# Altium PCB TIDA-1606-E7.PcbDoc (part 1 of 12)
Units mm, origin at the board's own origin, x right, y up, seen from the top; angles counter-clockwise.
Board outline 270 x 345 mm, 4 copper layers (Top Layer, Signal Layer 1, Signal Layer 2, Bottom Layer), stack 2.326 mm thick; 1282 components, 576 nets, 3628 pads, 4132 vias.
Unrouted connection lines stored in the file: 1719.
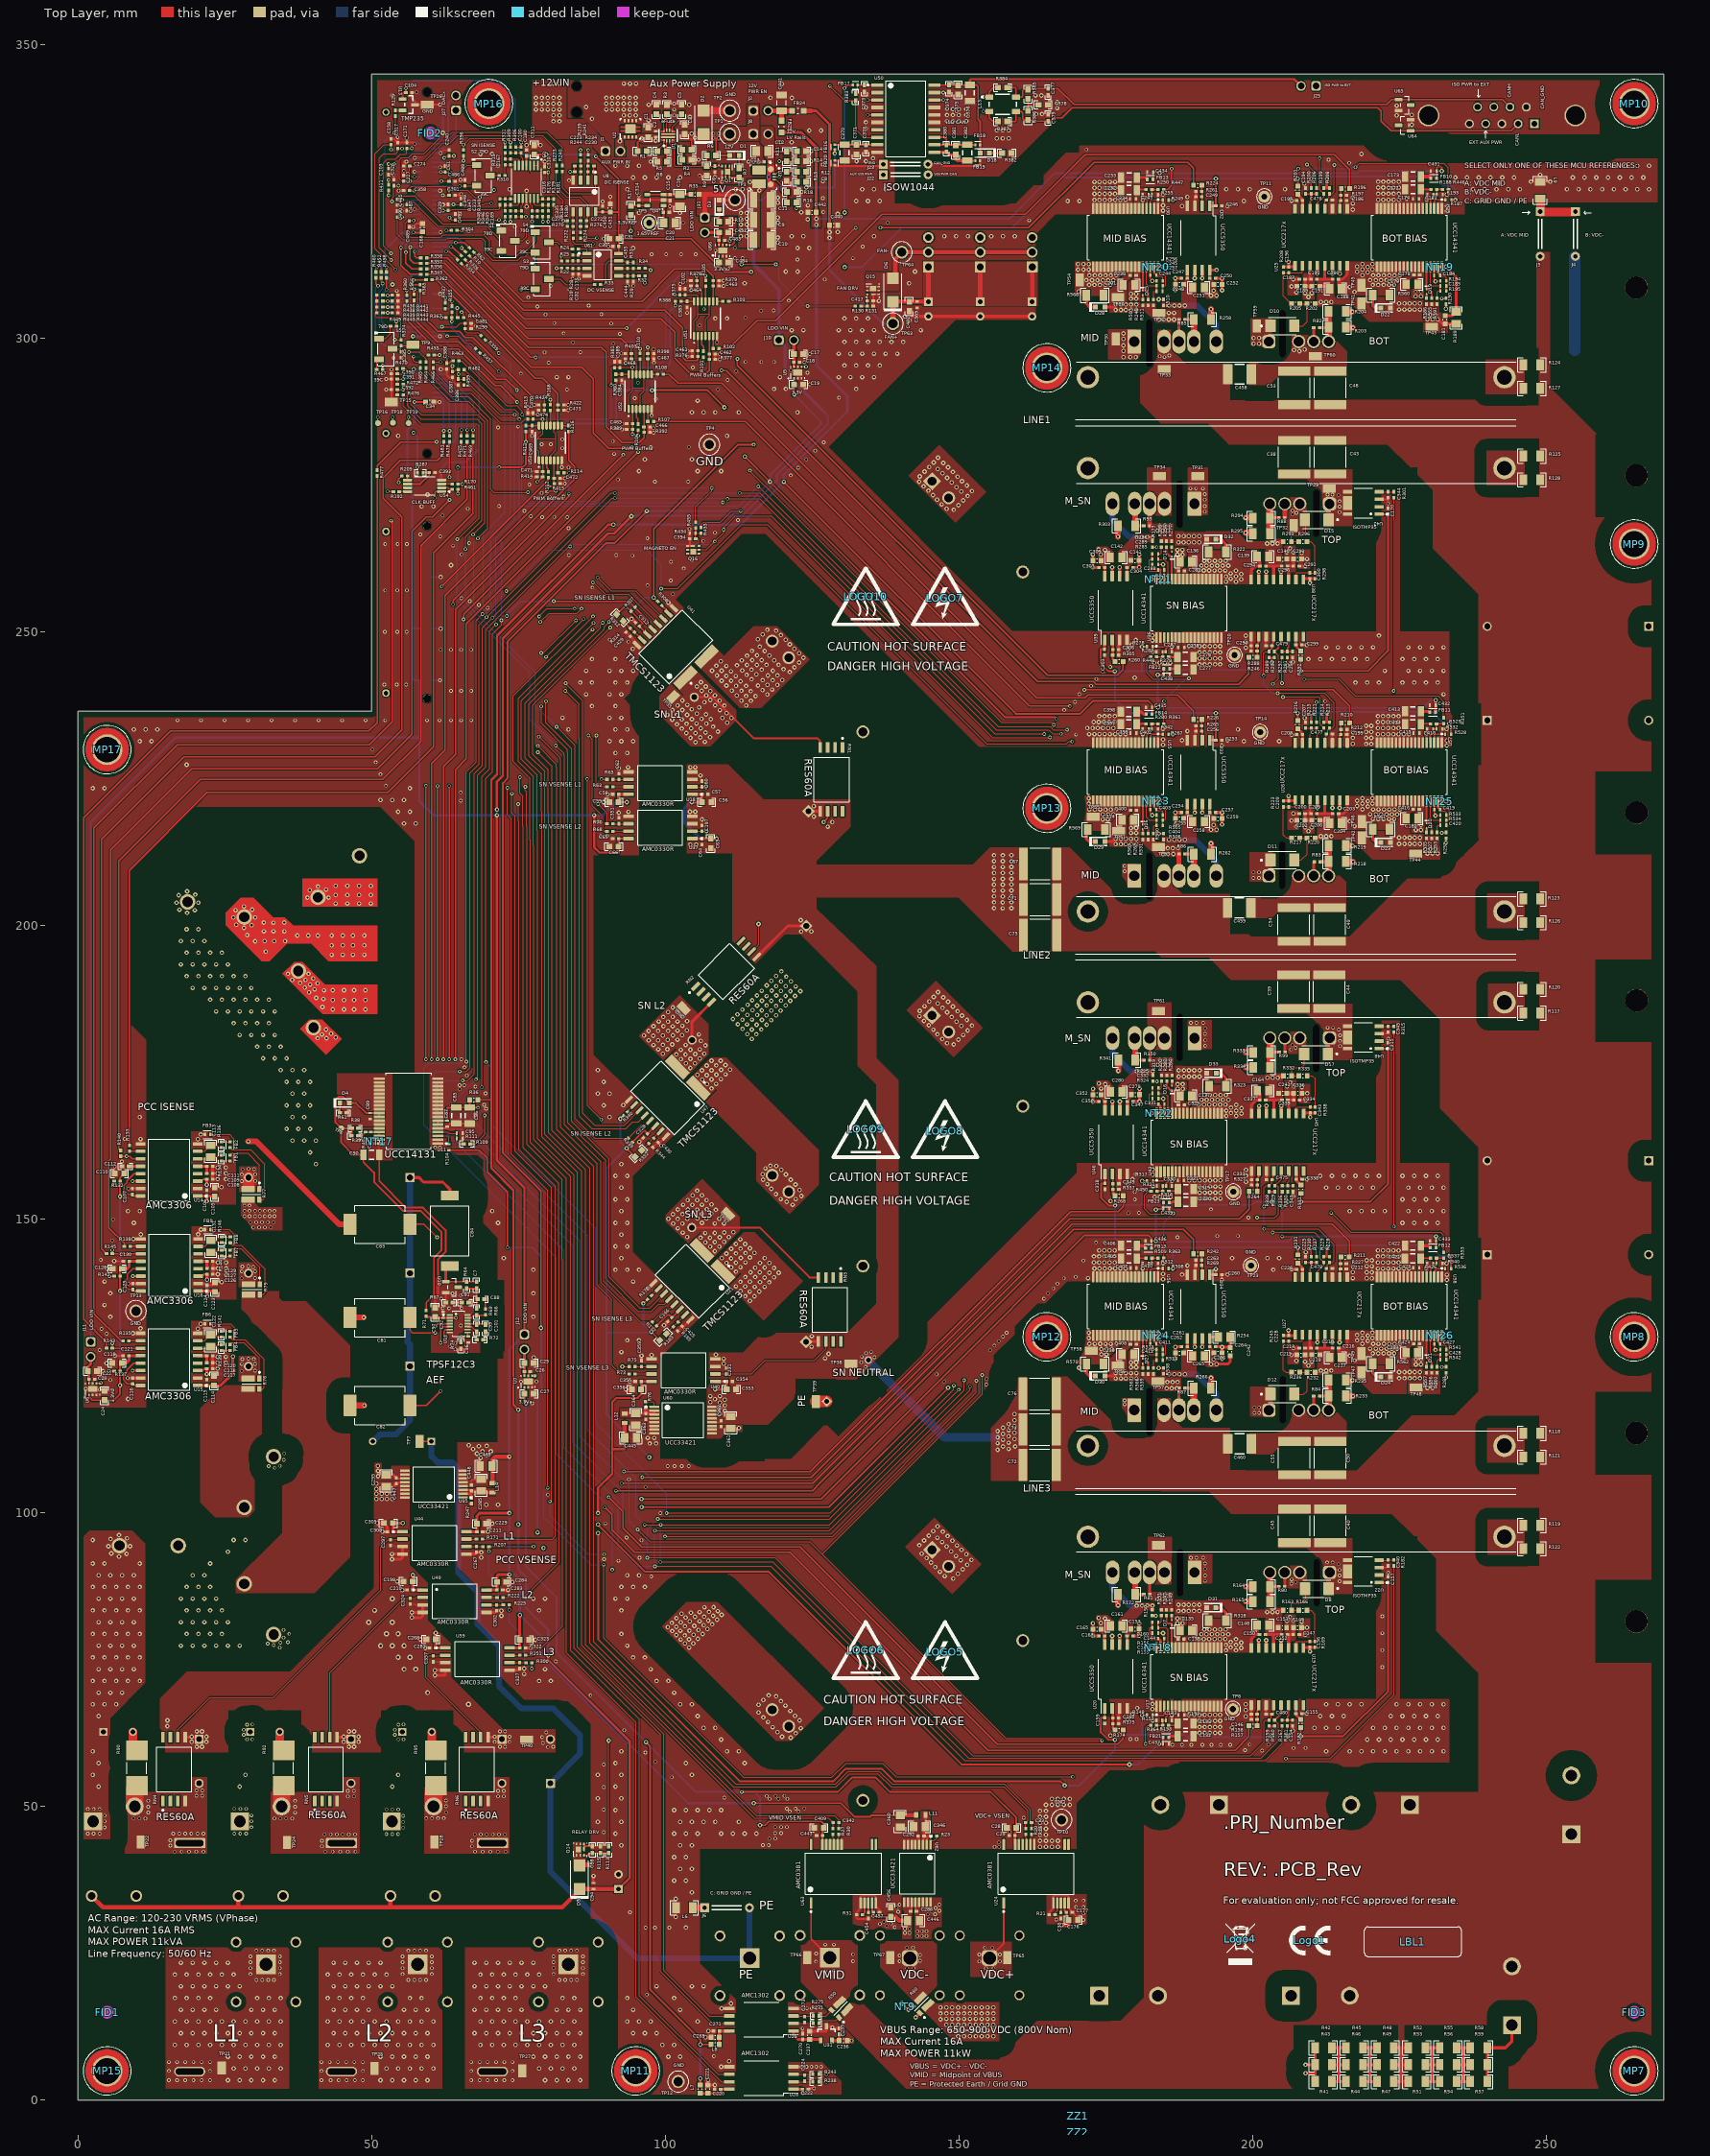
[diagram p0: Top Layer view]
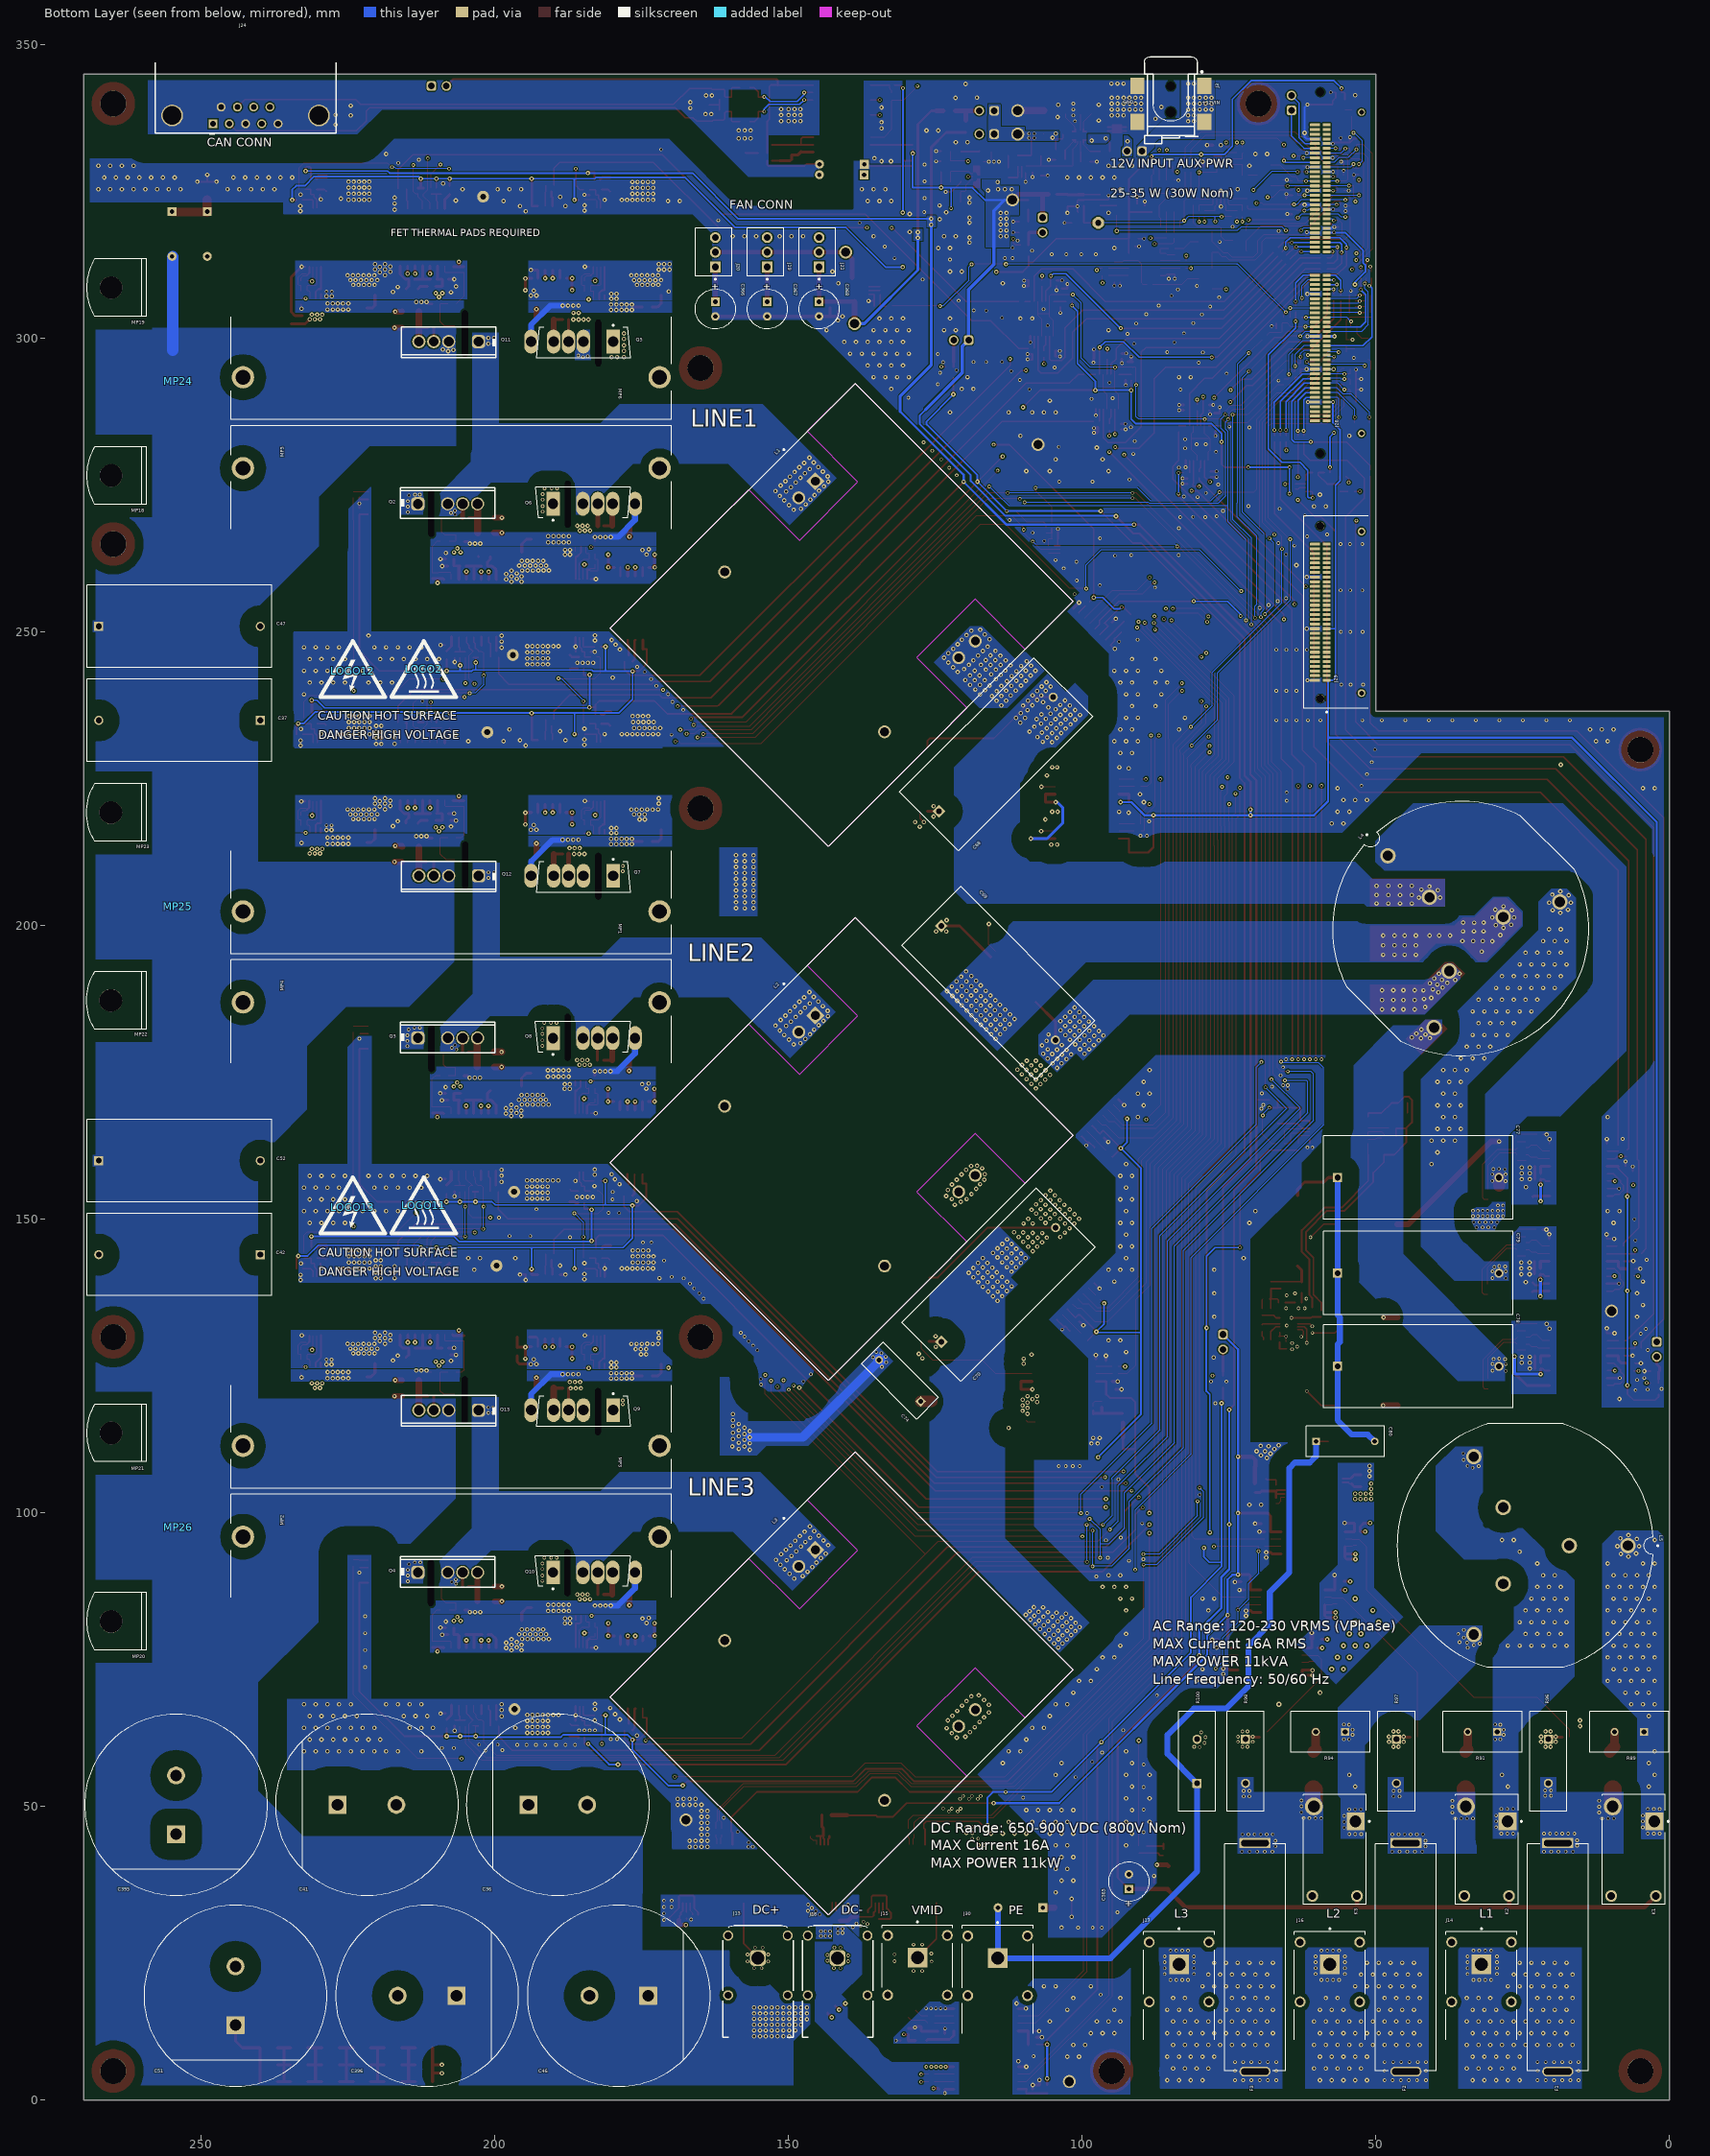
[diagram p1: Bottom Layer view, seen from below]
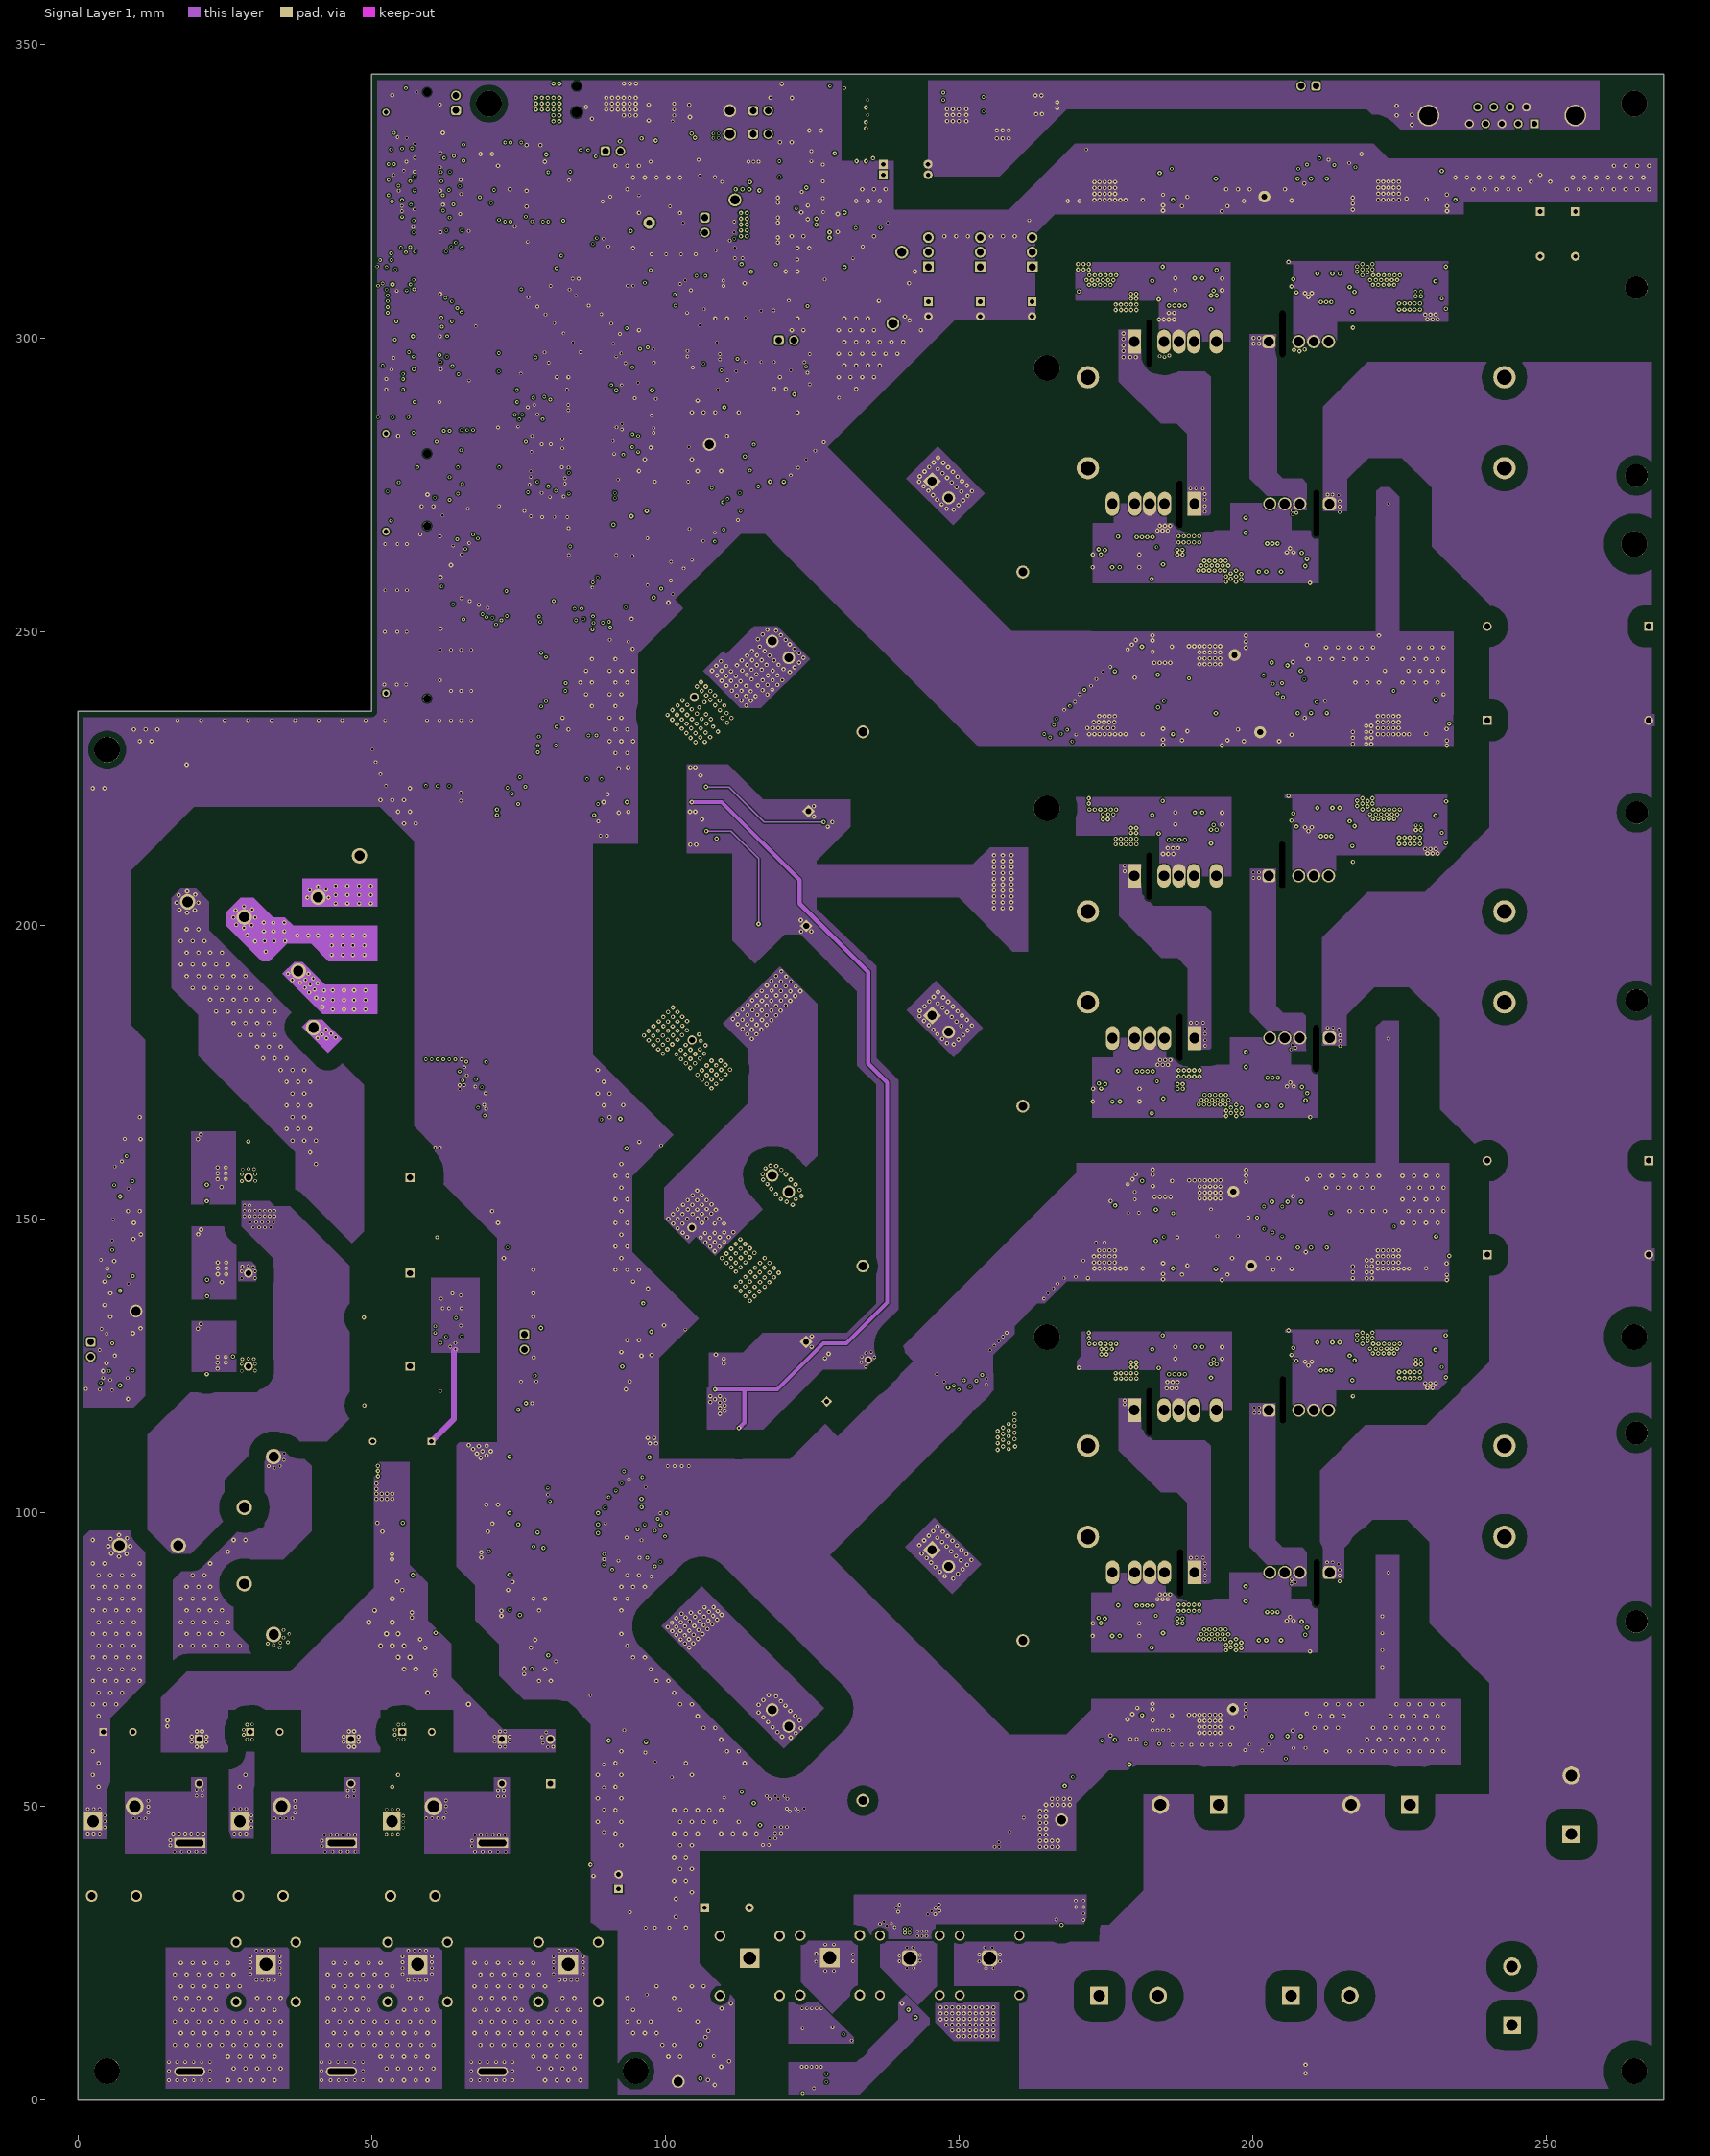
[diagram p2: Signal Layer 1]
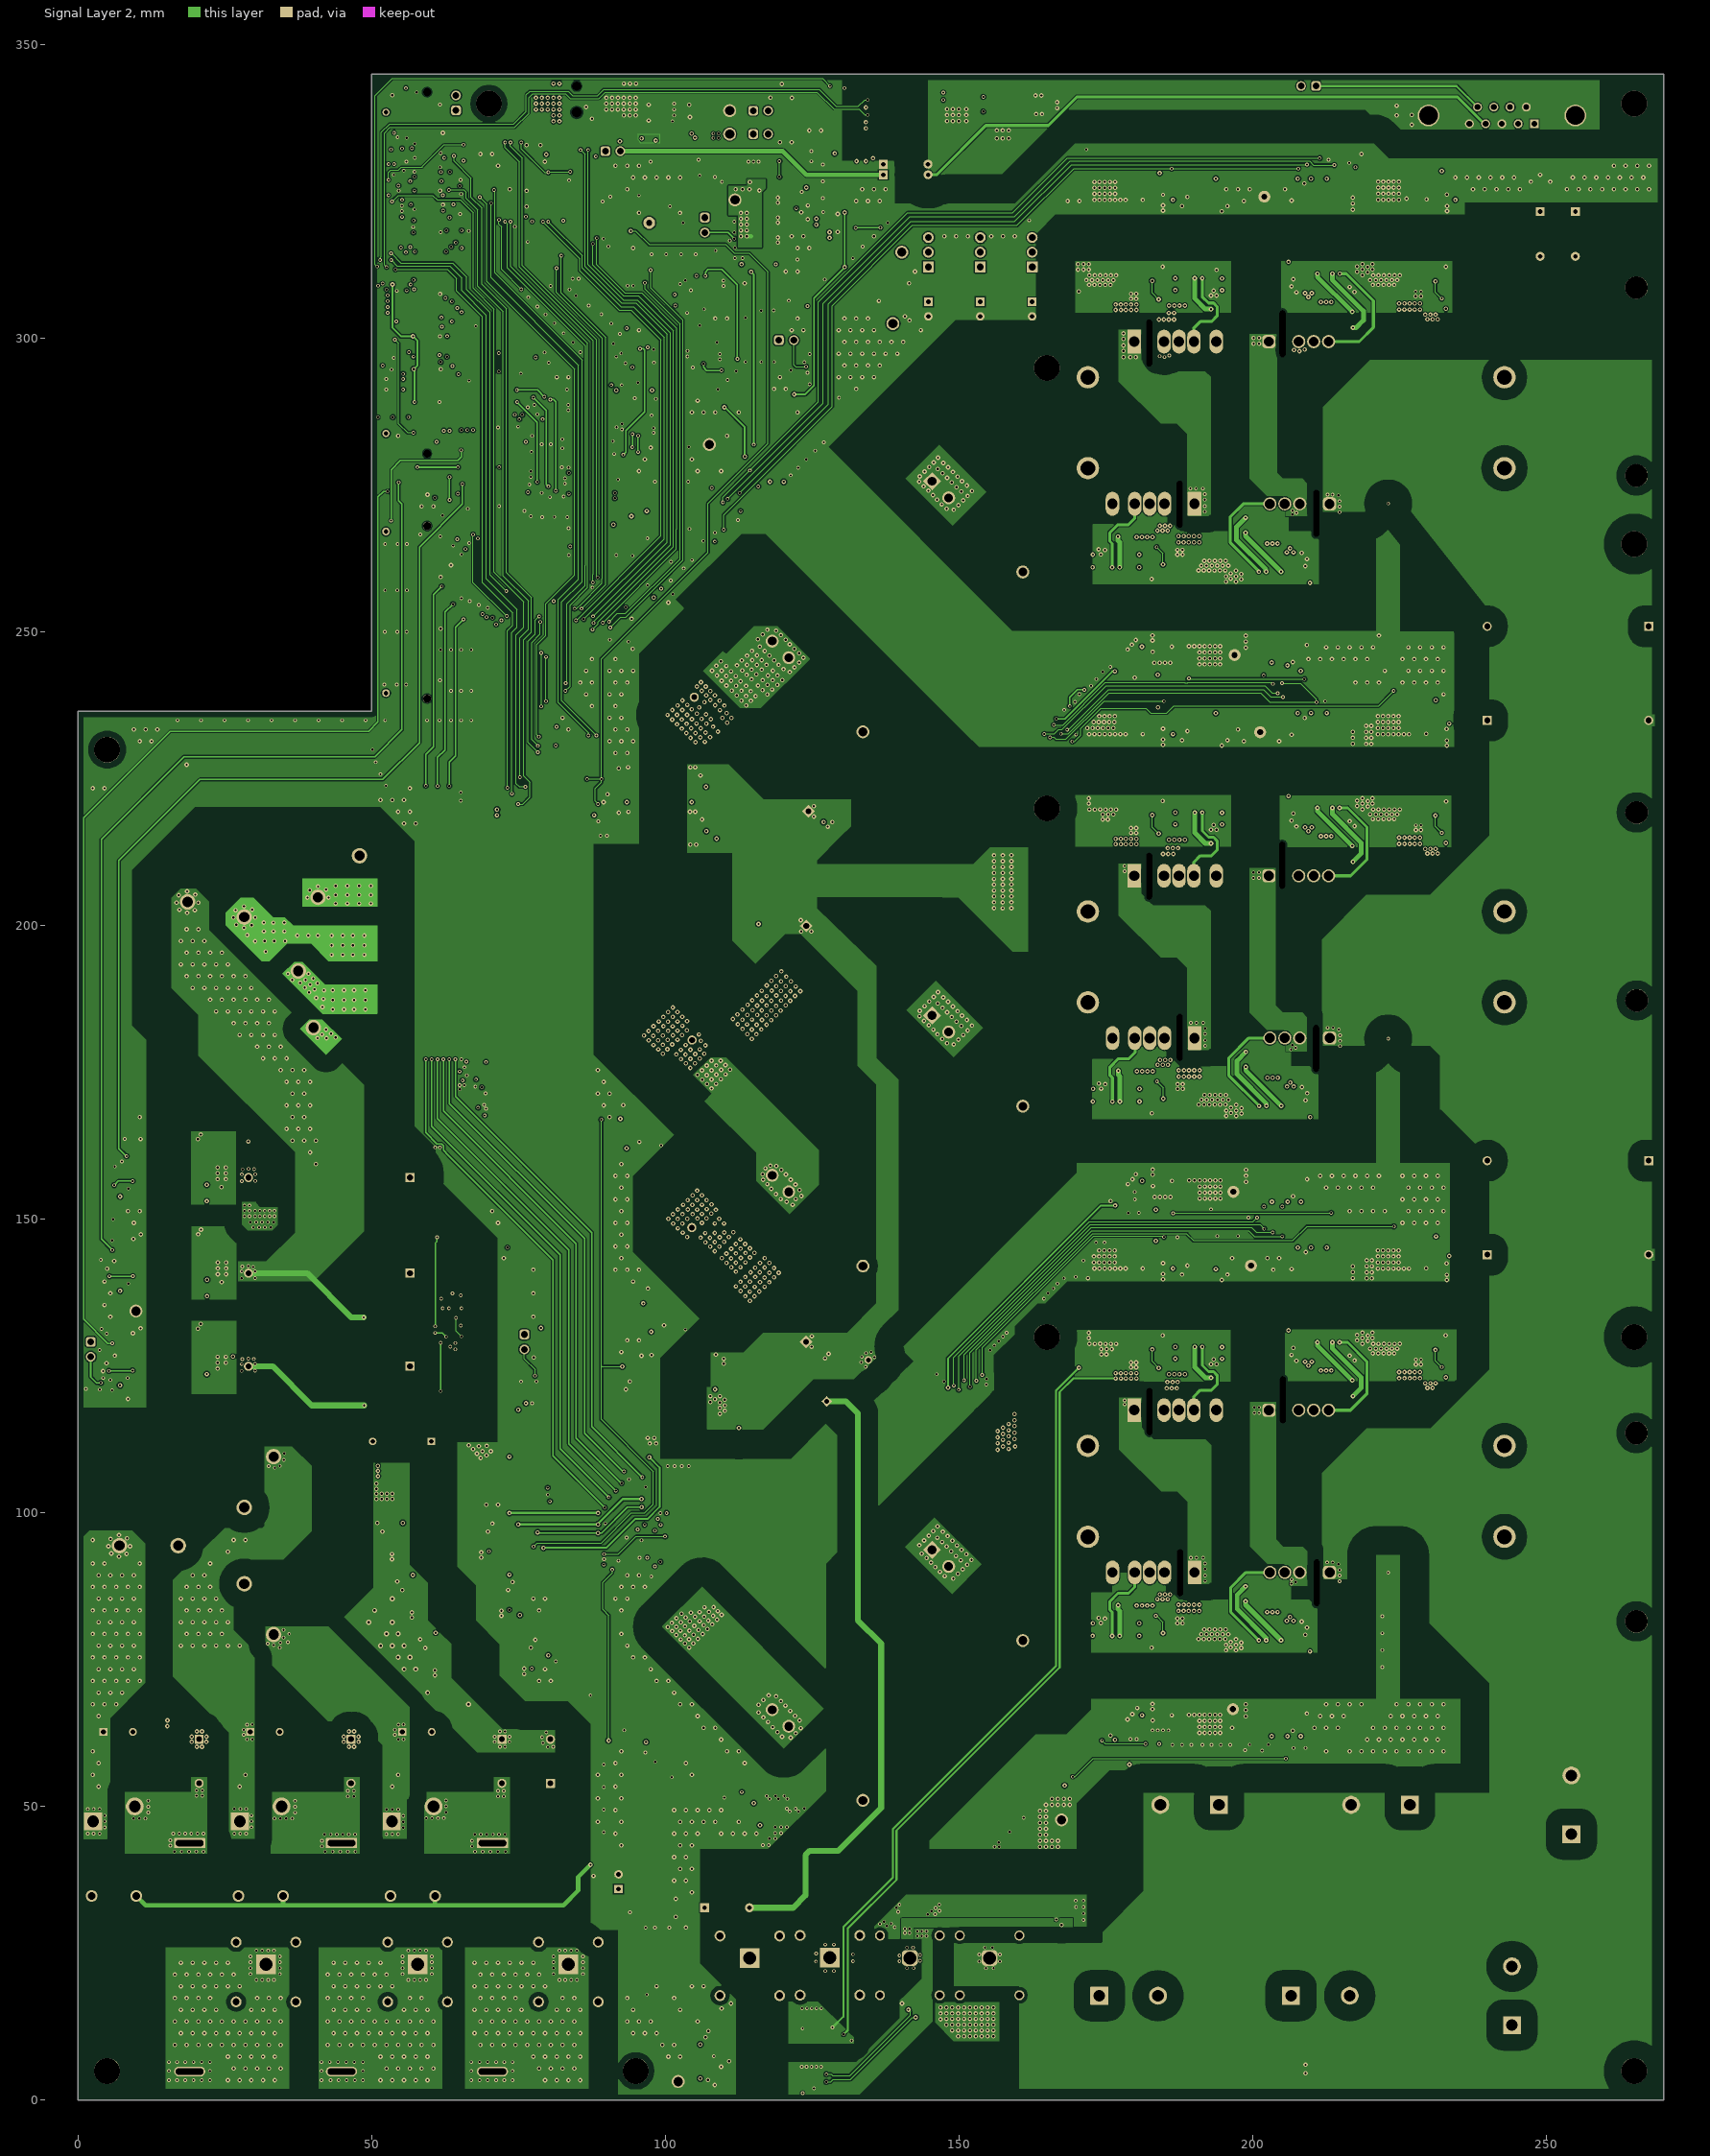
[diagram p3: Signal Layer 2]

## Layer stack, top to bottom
Top Solder: solder mask 0.01, Solder Resist, Dk 3.5
Top Layer: signal copper 0.06
Dielectric 1: prepreg 0.36, FR-4, Dk 4.2
Signal Layer 1: signal copper 0.07
Dielectric 2: core 1.3462, FR-4, Dk 4.2
Signal Layer 2: signal copper 0.07
Dielectric 3: prepreg 0.36, FR-4, Dk 4.2
Bottom Layer: signal copper 0.06
Bottom Solder: solder mask 0.01, Solder Resist, Dk 3.5

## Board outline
0,0 270.002,0 270,0 270,345 50,345 50,236.5 0,236.5

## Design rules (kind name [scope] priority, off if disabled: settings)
AcuteAngle AcuteAngle_room [InNet('+5V') and WithinRoom('Room_DCDC')] p1: minimum=1.00000000000000E+0001 checktracksonly=FALSE
AcuteAngle [All] p2: minimum=4.50000000000000E+0001 checktracksonly=TRUE
AssemblyTestPointUsage [All] p1: valid=2
BoardOutlineClearance BoardOutlineClearance_Poly [OnCopper and IsPoly] p1: gap=1 ignorepadtopadclearanceinfootprint=FALSE
BoardOutlineClearance [OnCopper and Not InComponentClass('Logo') and not InComponentClass('FiducialMark') and not InRegion(1000,500,4000,800) and not InPoly and not (StringText = '.Layer_Name')] p2: gap=0.5 ignorepadtopadclearanceinfootprint=FALSE
Clearance "NT room" [WithinRoom('NT_Room')] p1: gap=0.203 ignorepadtopadclearanceinfootprint=TRUE except(0.003: Arc-Arc Arc-Track Track-Track)
Clearance HV_I_V_SENSE_LOW [InNetClass('HV_VDC_LOW') vs InNetClass('HV_VDC_LOW')] p2: gap=0.203 ignorepadtopadclearanceinfootprint=TRUE
Clearance HV_I_SENSE_MID [InNetClass('HV_VDC_MID') vs InNetClass('HV_VDC_MID')] p3: gap=0.203 ignorepadtopadclearanceinfootprint=TRUE
Clearance HV_ISENSE_SN_PCC_1 [InNetClass('HV_L1') vs InNetClass('HV_L1')] p4: gap=0.203 ignorepadtopadclearanceinfootprint=TRUE
Clearance HV_ISENSE_SN_PCC_2 [InNetClass('HV_L2') vs InNetClass('HV_L2')] p5: gap=0.203 ignorepadtopadclearanceinfootprint=TRUE
Clearance HV_ISENSE_SN_PCC_3 [InNetClass('HV_L3') vs InNetClass('HV_L3')] p6: gap=0.203 ignorepadtopadclearanceinfootprint=TRUE
Clearance HV_VSENSE_SN [InNetClass('HV_VSEN_SN') vs InNetClass('HV_VSEN_SN')] p7: gap=0.203 ignorepadtopadclearanceinfootprint=TRUE
Clearance HV_VSENSE_PCC [InNetClass('HV_VSEN_PCC') vs InNetClass('HV_VSEN_PCC')] p8: gap=0.203 ignorepadtopadclearanceinfootprint=TRUE
Clearance HV_CAN [InNetClass('HV_CAN') vs InNetClass('HV_CAN')] p9: gap=0.203 ignorepadtopadclearanceinfootprint=TRUE
Clearance HV_AEF [InNetClass('AEF_GRID_GND') vs InNetClass('AEF_GRID_GND')] p10: gap=0.203 ignorepadtopadclearanceinfootprint=TRUE
Clearance HV_HV_1206_BleedR [InNetClass('HV_Nets') vs WithinRoom('Bleed_Room')] p11: gap=1.8 ignorepadtopadclearanceinfootprint=TRUE except(3: Arc-Fill Arc-Poly Arc-Region Track-Fill Track-Poly Track-Region SMDPad-Fill SMDPad-Poly SMDPad-Region THPad-Fill THPad-Poly THPad-Region Via-Fill Via-Poly Via-Region Fill-Fill Fill-Poly Fill-Region Poly-Poly Poly-Region Region-Region)
Clearance HV_Slot [InNetClass('HV_Nets') vs (ObjectKind = 'Pad') And (Net = 'No Net') And (Component = 'Free')] p12: gap=0.381 ignorepadtopadclearanceinfootprint=TRUE
Clearance HV_HV_Diode [HasFootprint('FP-US1Q-TP_SMA-MFG') vs InNetClass('HV_Nets') and ispad] p13: gap=2.8 ignorepadtopadclearanceinfootprint=TRUE except(2.4: SMDPad-SMDPad SMDPad-THPad)
Clearance HV_HV [InNetClass('HV_Nets') vs InNetClass('HV_Nets')] p14: gap=2.8 ignorepadtopadclearanceinfootprint=TRUE
Clearance HV_AC1 [InNetClass('HV_AC1') vs InNetClass('HV_AC1')] p15: gap=3 ignorepadtopadclearanceinfootprint=TRUE
Clearance GRID_GND_LV [InNet('GRID_GND') vs InNetClass('LV Nets')or InNetClass('LV_DIGITAL')] p16: gap=3 ignorepadtopadclearanceinfootprint=TRUE
Clearance GRID_AEF_LV [InNetClass('AEF_GRID_GND') vs InNetClass('LV Nets')or InNetClass('LV_DIGITAL')] p17: gap=3 ignorepadtopadclearanceinfootprint=TRUE
Clearance HV_LV_ISOTMP [InNetClass('HV_Nets') vs WithinRoom('RoomDefinition_ISOTMP_3')or WithinRoom('RoomDefinition_ISOTMP_2')or WithinRoom('RoomDefinition_ISOTMP_1')] p18: gap=3.8 ignorepadtopadclearanceinfootprint=TRUE
Clearance HV_LV [InNetClass('LV Nets') vs InNetClass('HV_Nets') or InNetClass('HV_AC1')] p19: gap=5 ignorepadtopadclearanceinfootprint=TRUE
Clearance HVAC_LV_Digital [InNetClass('LV_DIGITAL') vs InNetClass('HV_AC1')or InNetClass('HV_Nets')] p20: gap=5 ignorepadtopadclearanceinfootprint=TRUE
Clearance HV_Heatsink [InNetClass('HV_Nets') vs InNetClass('HV_Heatsink')] p21: gap=2 ignorepadtopadclearanceinfootprint=TRUE
Clearance HV_HW_Footprints_CLR [InNetClass('HV_Nets') vs HasFootprint('fp-613_MNT_BRACKET-MFG') or HasFootprint('FP-C247-075-3AE_PTH_HTSNK_75MM0_18MM0-MFG') or HasFootprint('FP-B181108 D6665 V2_PTH_IND_52MM5_59MM0-MFG')] p22: gap=1.5 ignorepadtopadclearanceinfootprint=TRUE
Clearance HV_HW_Footprints_CLR_1 [InNetClass('LV Nets') vs HasFootprint('fp-613_MNT_BRACKET-MFG') or HasFootprint('FP-C247-075-3AE_PTH_HTSNK_75MM0_18MM0-MFG') or HasFootprint('FP-B181108 D6665 V2_PTH_IND_52MM5_59MM0-MFG')] p23: gap=1.5 ignorepadtopadclearanceinfootprint=TRUE
Clearance HV_Footprints_CLR_Standoff [InNetClass('HV_Nets') vs HasFootprint('FP-9774040960R_ROUND_SPACER_6MM0-MFG')] p24: gap=3 ignorepadtopadclearanceinfootprint=TRUE
Clearance LV_Footprints_CLR_Standoff [HasFootprint('FP-9774040960R_ROUND_SPACER_6MM0-MFG') vs InNetClass('LV Nets')] p25: gap=1 ignorepadtopadclearanceinfootprint=TRUE
Clearance HV_Footprints_CONN_1 [InNetClass('All Nets') vs HasFootprint('Cliff_FCR7350R')or HasFootprint('Cliff_FCR7350B')] p26: gap=0.6 ignorepadtopadclearanceinfootprint=TRUE
Clearance HV_Footprints_CONN [InNetClass('All Nets') vs HasFootprint('FP-FCR7350Y_CONN_BANANA_JACK-MFG') or HasFootprint('FP-FCR7350N_CONN_BANANA_JACK-MFG') or HasFootprint('FP-FCR7350G_CONN_BANANA_JACK-MFG')] p27: gap=0.75 ignorepadtopadclearanceinfootprint=TRUE
Clearance LV_HF [InNetClass('LV_HF') vs InNetClass('All Nets')] p28: gap=0.4 ignorepadtopadclearanceinfootprint=TRUE
Clearance LV_LV [InNetClass('LV_DIGITAL') vs InNetClass('LV Nets')or InNetClass('LV_DIGITAL')] p29: gap=0.203 ignorepadtopadclearanceinfootprint=TRUE
Clearance Room_CLR_efuse [WithinRoom('Room_eFuse')] p30: gap=0.203 ignorepadtopadclearanceinfootprint=TRUE except(0.152: Arc-Via Arc-Text Track-Via Track-Text SMDPad-Via SMDPad-Text THPad-Via THPad-Text Via-Via Via-Text Fill-Text Poly-Text Region-Text Text-Text; 0.196: SMDPad-Fill SMDPad-Poly SMDPad-Region THPad-Fill THPad-Poly THPad-Region Via-Fill Via-Poly Via-Region)
Clearance Room_CLR_LDO [WithinRoom('LDORoom_1') or WithinRoom('LDORoom_2') or WithinRoom('LDORoom_3') or WithinRoom('LDORoom_4')] p31 off: gap=0.114 ignorepadtopadclearanceinfootprint=TRUE
Clearance Room_CLR_DCDC [WithinRoom('Room_DCDC')] p32: gap=0.178 ignorepadtopadclearanceinfootprint=TRUE except(0.089: Fill-Region; 0.102: SMDPad-Region; 0.254: Arc-Poly Track-Poly SMDPad-Poly THPad-Poly Via-Poly Fill-Poly Poly-Poly)
Clearance Clearance_Poly_Efuse [InPolygon vs InNet('+12V_OUT')or InNet('VIN_PWR')] p33: gap=0.152 ignorepadtopadclearanceinfootprint=TRUE
Clearance Clearance_FiducialMark [IsKeepOut and InComponentClass('FiducialMark') vs InComponentClass('FiducialMark') and ispad] p34: gap=0 ignorepadtopadclearanceinfootprint=FALSE
Clearance Clearance_Keepouts [((IsTrack Or IsArc) And Not InPoly) And IsFree and IsKeepOut vs ((IsTrack Or IsArc) And Not InPoly) And IsFree and IsKeepOut] p35: gap=0 ignorepadtopadclearanceinfootprint=FALSE
Clearance Clearance_Keepouts_1 [(ObjectKind = 'Pad') And (Net = 'No Net') vs IsKeepOut] p36: gap=0 ignorepadtopadclearanceinfootprint=FALSE
Clearance Clearance_Keepouts_2 [All vs IsKeepOut] p37: gap=0.5 ignorepadtopadclearanceinfootprint=FALSE
Clearance [All] p38: gap=0.203 ignorepadtopadclearanceinfootprint=TRUE
ComponentClearance ComponentClearance_3DBody [(ObjectKind = '3D Body') And (Identifier = 'TMDSCNCD280039C_PCB')] p1: gap=-0.025 collisioncheckmode=3 verticalgap=0.254 showdistances=FALSE
ComponentClearance ComponentClearance_HeatSink_FET_1 [HasFootprint('FP-C247-075-3AE_PTH_HTSNK_75MM0_18MM0-MFG')] p2: gap=-0.254 collisioncheckmode=3 verticalgap=-0.254 showdistances=TRUE
ComponentClearance ComponentClearance_THtoTH [IsThruComponent vs IsThruComponent] p3: gap=0.508 collisioncheckmode=3 verticalgap=0.762 showdistances=FALSE
ComponentClearance ComponentClearance_Net-tie [(ComponentType = 'Net Tie')] p4: gap=-0.025 collisioncheckmode=3 verticalgap=0.254 showdistances=FALSE
DiffPairsRouting [All] p1: maxlimit=2.54 minlimit=0.254 mostfreqgap=0.254 toplayer_minwidth=0.381 toplayer_maxwidth=0.381 toplayer_prefwidth=0.381 midlayer1_minwidth=0.381 midlayer1_maxwidth=0.381 midlayer1_prefwidth=0.381 midlayer2_minwidth=0.381 midlayer2_maxwidth=0.381 midlayer2_prefwidth=0.381 bottomlayer_minwidth=0.381 bottomlayer_maxwidth=0.381 bottomlayer_prefwidth=0.381 maxuncoupledlength=25.4
FabricationTestPointUsage TestPointUsage [All] p1: valid=2 allowmultiple=FALSE
FabricationTestpoint Testpoint [All] p1: side=3 testpointundercomponent=TRUE minsize=1.016 maxsize=2.54 preferedsize=1.524 minholesize=0 maxholesize=1.016 preferedholesize=0.813 testpointgrid=0.025 allowsidetop=TRUE allowsidebottom=TRUE usegrid=TRUE gridtolerance=0
FanoutControl Fanout_LCC [IsLCC] p1: bgadir=Out bgaviamode=Centered fanoutstyle=Auto fanoutdirection=Alternating viagrid=0.025 // Fanout_LCC (Default Rule)
FanoutControl Fanout_BGA [IsBGA] p2: bgadir=Out bgaviamode=Centered fanoutstyle=Auto fanoutdirection=Alternating viagrid=0.025 // Fanout_BGA (Default Rule)
FanoutControl Fanout_Default [All] p4: bgadir=Out bgaviamode=Centered fanoutstyle=Auto fanoutdirection=Alternating viagrid=0.025 // Fanout_Default (Default Rule)
FanoutControl Fanout_Small [(CompPinCount < 5)] p5: bgadir=Out bgaviamode=Centered fanoutstyle=Auto fanoutdirection=OutThenIn viagrid=0.025 // Fanout_Small (Default Rule)
HoleSize [All] p1: absolutevalues=TRUE maxlimit=8.2 minlimit=0.152 maxpercent=80.000 minpercent=20.000
MinimumAnnularRing MinimumAnnularRing_Room [WithinRoom('Romm_TVS')or WithinRoom('Room_eFuse')] p1: minimumring=0.076
MinimumAnnularRing [All] p2: minimumring=0.127
MinimumAnnularRing MinimumAnnularRing_ThermalPadVias [IsVia and InAnyComponent] p3: minimumring=0.15
MinimumSolderMaskSliver MinimumSolderMaskSliver_Logo [InComponentClass('Logo') vs InComponentClass('Logo')] p1: minsoldermaskwidth=0.018
MinimumSolderMaskSliver [All] p2: minsoldermaskwidth=0.064
PlaneConnect [All] p1: planeconnectstyle=Relief reliefexpansion=0.254 reliefentries=4 reliefconductorwidth=0.254 reliefairgap=0.254
PolygonConnect [All] p1: connectstyle=Direct reliefconductorwidth=0.254 reliefentries=4 polygonreliefangle="90 Angle" airgapwidth=0.254
RoomDefinition NT_Room [False] p1: confinementstyle=ConfineIn formatcopy=TRUE lockcomponents=FALSE outline 139.852,16.764 141.961,16.764 141.961,14.935 139.852,14.935
RoomDefinition Bleed_Room [False] p2: confinementstyle=ConfineIn formatcopy=TRUE lockcomponents=FALSE outline 203.251,13.716 243.815,13.716 243.815,0.965 203.251,0.965
RoomDefinition Romm_TVS [False] p3: confinementstyle=ConfineIn formatcopy=TRUE lockcomponents=FALSE outline 92.12,337.5 96.25,337.5 96.25,333.825 92.12,333.825
RoomDefinition Room_DCDC [False] p4: confinementstyle=ConfineIn formatcopy=TRUE lockcomponents=FALSE outline 114.619,329.603 119,329.603 119,325.453 114.619,325.453
RoomDefinition RoomDefinition_ISOTMP_2 [False] p5: confinementstyle=ConfineIn formatcopy=TRUE lockcomponents=FALSE outline 215.329,183.361 225.995,183.361 225.995,176.861 215.329,176.861
RoomDefinition RoomDefinition_ISOTMP_1 [False] p6: confinementstyle=ConfineIn formatcopy=TRUE lockcomponents=FALSE outline 215.253,274.376 225.918,274.376 225.918,267.876 215.253,267.876
RoomDefinition RoomDefinition_ISOTMP_3 [False] p7: confinementstyle=ConfineIn formatcopy=TRUE lockcomponents=FALSE outline 215.129,92.9 225.795,92.9 225.795,86.4 215.129,86.4
RoomDefinition Room_eFuse [InComponentClass('U_TIDA-1606-E6_Hardware')] p8: confinementstyle=ConfineIn formatcopy=TRUE lockcomponents=FALSE outline 99.067,335.951 102.046,335.951 102.046,333.175 99.067,333.175
RoutingVias Room_RoutingVias [WithinRoom('Romm_TVS')or WithinRoom('Room_eFuse')] p1: holewidth=0.305 width=0.61 viastyle="Through Hole" minholewidth=0.152 minwidth=0.254 maxholewidth=1.016 maxwidth=1.651
RoutingVias ThermalPadVias [IsVia and InAnyComponent] p2: holewidth=0.305 width=0.508 viastyle="Through Hole" minholewidth=0.198 minwidth=0.381 maxholewidth=1.016 maxwidth=0.61
RoutingVias [All] p3: holewidth=0.305 width=0.61 viastyle="Through Hole" minholewidth=0.254 minwidth=0.508 maxholewidth=1.016 maxwidth=1.651
SilkToBoardRegionClearance [Not ((IsComment or IsDesignator) And (Hide <> 'False')) and not InRegion(1000,500,4000,800)] p1:
SilkToSilkClearance SilkToSilkClearance_Pb-FreeLogo [(HasFootprint('Pb-Free_Overlay_Medium') OR HasFootprint('Pb-Free_Overlay_Small')) vs (HasFootprint('Pb-Free_Overlay_Medium') OR HasFootprint('Pb-Free_Overlay_Small'))] p1: silktosilkclearance=0
SilkToSilkClearance [All] p2: silktosilkclearance=0.076
SilkToSolderMaskClearance SilkToSolderMasPad_CLR_Exception [IsPad vs InComponent('J1')] p1 off: minsilkscreentomaskgap=0 clearancetoexposedcopper=TRUE
SilkToSolderMaskClearance SilkToComponentPadClearance [(ObjectKind = 'Pad') And (Component = 'Free')] p2: minsilkscreentomaskgap=0 clearancetoexposedcopper=TRUE
SilkToSolderMaskClearance SilkToComponentPadClearance_1 [IsPad and not (Component = 'Free') vs not IsArc] p3: minsilkscreentomaskgap=0.006 clearancetoexposedcopper=TRUE
SilkToSolderMaskClearance "Silk to Solder Mask Opening" [IsPad vs not IsArc] p4: minsilkscreentomaskgap=0.025 clearancetoexposedcopper=FALSE
SolderMaskExpansion [All] p1: expansion=0.05
UnRoutedNet [All] p1: checkbadconnections=TRUE
Width [InNetClass('All Nets')] p1: maxlimit=7 minlimit=0.127 preferedwidth=0.152
14 further rules are at their usual default settings.

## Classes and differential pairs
net class AEF_GRID_GND: +12V_AEF_ISO AEF_INJ AEF_INJ_CM AEF_SENS1 AEF_SENS2 AEF_SENS3 AEF_TVS_PT AEF_VDD FB_AEF GRID_GND NetC88_1 NetC91_1 NetC99_1 NetC99_2 NetC101_1 NetD4_1 NetR38_1 NetU10_3 NetU12_1 NetU12_3 NetU12_12 VEEA_UCC_AEF
net class HV_CAN: CAN_GND2 CANH CANHI CANL CANLO GND_ISO_CAN NetC378_2 NetD18_1 NetJ24_1 NetJ24_8 NetU50_14 NetU64_3 NetU65_3 VIN_PWR_CAN VISOOUT VP_CAN VP_CAN_SUBD
net class HV_VDC_MID: 3.3V_ISO_MID3 +15V_MID1 +15V_MID2 +15V_MID3 -4V_MID1 -4V_MID2 -4V_MID3 FBVDD_MID1 FBVDD_MID2 FBVDD_MID3 FBVEE_MID1 FBVEE_MID2 FBVEE_MID3 GATE_MID_L1 GATE_MID_L2 GATE_MID_L3 I_MID+ I_MID- NetD25_2 NetD26_2 NetD27_2 NetD28_1 NetD29_1 NetD30_1 OUTH_MID_L1 OUTH_MID_L2 OUTH_MID_L3 REF_MID1 REF_MID2 REF_MID3 RLIM_MID1 RLIM_MID2 RLIM_MID3 VDC_MID VDC_MID_IN VEEA_MID1 VEEA_MID2 VEEA_MID3 VINN_VMD VINP_VMD
net class HV_VDC_LOW: +5VISO_DC- +15V_VDC-1 +15V_VDC-2 +15V_VDC-3 -4V_VDC-1 -4V_VDC-2 -4V_VDC-3 FBVDD_VDC-1 FBVDD_VDC-2 FBVDD_VDC-3 FBVEE_VDC-1 FBVEE_VDC-2 FBVEE_VDC-3 GATE_BOT_L1 GATE_BOT_L2 GATE_BOT_L3 I_NEG_RAIL+ I_NEG_RAIL- NetC35_2 NetC196_1 NetC209_1 NetC228_1 NetC454_2 NetD10_2 NetD11_2 NetD12_2 NetD19_2 NetD20_2 NetD21_2 NetD22_1 NetD23_1 NetD24_1 NetR21_1 NetR31_1 OH_BOT_L1 OH_BOT_L2 OH_BOT_L3 OL_BOT_L1 OL_BOT_L2 OL_BOT_L3 REF_VDC-1 REF_VDC-2 REF_VDC-3 RLIM_VDC-1 RLIM_VDC-2 RLIM_VDC-3 VDC- VDC-_REF VDC_NEG_IN VEEA_VDC-1 VEEA_VDC-2 VEEA_VDC-3 VINN_DC- VINP_DC-
net class HV_VSEN_PCC: +5VISO_PCC V_PCC_IN1 V_PCC_IN2 V_PCC_IN3 V_PCC_N
net class HV_VSEN_SN: +5VISO_SN NetRN3_7 NetRN3_8 V_SN_IN1 V_SN_IN2 V_SN_IN3 V_SN_N
net class LV_HF: GATE_MID_L1 GATE_MID_L2 GATE_MID_L3 GATE_MID_SN_L1 GATE_TOP_L1 OUTH_MID_L1 OUTH_MID_L2 OUTH_MID_L3 OUTH_MID_SN_L1 OUTH_TOP_L1 OUTL_TOP_L1
net class LV_DIGITAL: \EN_DCDC_GATES BUFF_EN CAN_EN CAN_RX CAN_TX CANEN_IO CANRX_IO CANTX_IO EN_DC_IO EN_DCDC_GATES_BUF EN_RY_IO FAN_CTRL FAN_CTRL_BU FLT_BU G_FLT1_IO G_FLT2_IO G_FLT3_IO G_RDY_IO G_RST_IO GATES_FLT_L1 GATES_FLT_L2 GATES_FLT_L3 GATES_RDY GATES_RST ID_A ID_B ID_C ID_D NetJ26_45 NetJ26_46 NetJ26_50 NetJ26_58 NetJ26_60 NetJ26_64 NetR437_1 OC1_IO OC2_IO OC3_IO OC_L1 OC_L2 OC_L3 PIN76 PIN96 PWM1_BUF_L1 PWM1_BUF_L2 PWM1_BUF_L3 PWM1_L1 PWM1_L2 PWM1_L3 PWM1L1 PWM1L2 PWM1L3 PWM2_BUF_L1 PWM2_BUF_L2 PWM2_BUF_L3 PWM2_L1 PWM2_L2 PWM2_L3 PWM2L1 PWM2L2 PWM2L3 PWM3_BUF_L1 PWM3_BUF_L2 PWM3_BUF_L3 PWM3_L1 PWM3_L2 PWM3_L3 PWM3L1 PWM3L2 PWM3L3 PWM4_BUF_L1 PWM4_BUF_L2 PWM4_BUF_L3 PWM4_L1 PWM4_L2 PWM4_L3 PWM4L1 PWM4L2 PWM4L3 RY_N SD_CLKI SD_CLKI_IN_L1 SD_CLKI_IN_L2 SD_CLKI_IN_L3 SD_CLKI_OUT_L1 SD_CLKI_OUT_L2 SD_CLKI_OUT_L3 SD_Data_I_PCC_L1 SD_Data_I_PCC_L2 SD_Data_I_PCC_L3
net class "LV Nets": 1.65V 3.3VREF +3V3 +3V3_Ua +3V3_Ua2 +3V3_Ud +5V +12V +12V_FAN ALERT_L1 ALERT_L2 ALERT_L3 AMC1302_OUTN_A AMC1302_OUTN_B AMC1302_OUTP_A AMC1302_OUTP_B CAN_EN CAN_GND1 CAN_RX CAN_TX CAN_VDD CAN_VIO DC_RVSEN+ DC_RVSEN- DC_VSEN+ DC_VSEN- DCM_RVSEN+ DCM_RVSEN- DCM_VSEN+ DCM_VSEN- GND I_SENSE_SN_L1 I_SENSE_SN_L2 I_SENSE_SN_L3 I_SENSE_VDC_MID I_SENSE_VDC_NEG NetC100_2 NetC167_2 NetC169_2 NetC313_2 NetC316_2 NetC335_2 NetJ26_89 NetR23_2 OC_L1 OC_L2 OC_L3 OP_ISN1 OP_ISN2 OP_ISN3 PIN25_AIN PIN27_AIN PIN34_AIN PIN36_AIN PIN40_AIN SN_Relays TEMP_SENSE_AMB TEMP_SENSE_L1 TEMP_SENSE_L2 TEMP_SENSE_L3 TMCS_VO_L1 TMCS_VO_L2 TMCS_VO_L3 TMCS_VREF1 TMCS_VREF2 TMCS_VREF3 V_SENSE_MID_DC- V_SENSE_MID_DC-_0039C V_SENSE_PCC_L1 V_SENSE_PCC_L2 V_SENSE_PCC_L3 V_SENSE_SN_L1 V_SENSE_SN_L2 V_SENSE_SN_L3 VIN_PWR VINP_DC-_HAVOK
net class HV_Heatsink: MP1 MP2 MP3 MP4 MP5 MP6 NetMP1_2 NetMP2_1 NetMP3_2 NetMP4_1 NetMP5_1 NetMP6_2
net class HV_L3: +15V_SN_L3 -4V_SN_L3 AEF_CHK_3 AMC_DC_OUT3 AMC_HGND_L3 CHK_3 DESAT_BOT_L3 FBVDD_SN_L3 FBVEE_SN_L3 GATE_MID_SN_L3 GATE_TOP_L3 I_PCC_INN_L3 I_PCC_INP_L3 I_PCC_L3+ I_PCC_L3- I_SN_L3+ I_SN_L3- NetC127_1 NetC156_1 NetD7_2 NetD8_2 NetD31_1 NetFB7_2 NetFB8_2 OUTH_MID_SN_L3 OUTH_TOP_L3 OUTL_TOP_L3 REF_SN_L3 RLIM VEEA_SN_L3
net class HV_L2: +15V_SN_L2 -4V_SN_L2 AEF_CHK_2 AMC_DC_OUT2 AMC_HGND_L2 CHK_2 DESAT_BOT_L2 FBVDD_SN_L2 FBVEE_SN_L2 GATE_MID_SN_L2 GATE_TOP_L2 I_PCC_INN_L2 I_PCC_INP_L2 I_PCC_L2+ I_PCC_L2- I_SN_L2+ I_SN_L2- NetC118_1 NetC343_1 NetD16_2 NetD17_2 NetD33_1 NetFB4_2 NetFB5_2 OUTH_MID_SN_L2 OUTH_TOP_L2 OUTL_TOP_L2 REF_SN_L2 RLIM_SN_L2 VEEA_SN_L2
net class HV_L1: +15V_SN_L1 -4V_SN_L1 AEF_CHK_1 AMC_DC_OUT1 AMC_HGND_L1 CHK_1 DESAT_BOT_L1 FBVDD_SN_L1 FBVEE_SN_L1 GATE_MID_SN_L1 GATE_TOP_L1 I_PCC_INN_L1 I_PCC_INP_L1 I_PCC_L1+ I_PCC_L1- I_SN_L1+ I_SN_L1- NetC109_1 NetD14_2 NetD15_2 NetD32_1 NetFB1_2 NetFB2_2 OC_TOP_L1 OUTH_MID_SN_L1 OUTH_TOP_L1 OUTL_TOP_L1 REF_SN_L1 RLIM_SN_L1 VEEA_SN_L1
net class HV_AC1: +5VISO_PCC +5VISO_SN +12V_AEF_ISO AEF_CHK_1 AEF_CHK_2 AEF_CHK_3 AEF_CHK_N AEF_INJ AEF_INJ_CM AEF_SENS1 AEF_SENS2 AEF_SENS3 AEF_TVS_PT AEF_VDD AMC_DC_OUT1 AMC_DC_OUT2 AMC_DC_OUT3 AMC_HGND_L1 AMC_HGND_L2 AMC_HGND_L3 CHK_1 CHK_2 CHK_3 FB_AEF GRID_GND I_PCC_INN_L1 I_PCC_INN_L2 I_PCC_INN_L3 I_PCC_INP_L1 I_PCC_INP_L2 I_PCC_INP_L3 I_PCC_L1+ I_PCC_L1- I_PCC_L2+ I_PCC_L2- I_PCC_L3+ I_PCC_L3- I_SN_L1+ I_SN_L1- I_SN_L2+ I_SN_L2- I_SN_L3+ I_SN_L3- NetC88_1 NetC91_1 NetC99_1 NetC99_2 NetC101_1 NetC109_1 NetC118_1 NetC127_1 NetD4_1 NetFB1_2 NetFB2_2 NetFB4_2 NetFB5_2 NetFB7_2 NetFB8_2 NetR38_1 PCC_L1 PCC_L2 PCC_L3 PTCR_L1 PTCR_L2 PTCR_L3 RLAY_1 RLAY_2 RLAY_3 V_PCC_IN1 V_PCC_IN2 V_PCC_IN3 V_PCC_L1 V_PCC_L2 V_PCC_L3 V_PCC_N V_SN_IN1 V_SN_IN2 V_SN_IN3 V_SN_N VEEA_UCC_AEF
net class STAND_OFFS: NetMP7_1 NetMP8_1 NetMP9_1 NetMP10_1 NetMP11_1 NetMP12_1 NetMP13_1 NetMP14_1 NetMP15_1 NetMP16_1 NetMP17_1
net class HV_Nets: 3.3V_ISO_MID3 +5VISO_DC- +15V_MID1 +15V_MID2 +15V_MID3 +15V_SN_L1 +15V_SN_L2 +15V_SN_L3 +15V_VDC-1 +15V_VDC-2 +15V_VDC-3 -4V_MID1 -4V_MID2 -4V_MID3 -4V_SN_L1 -4V_SN_L2 -4V_SN_L3 -4V_VDC-1 -4V_VDC-2 -4V_VDC-3 AEF_CHK_N CAN_GND2 CANH CANHI CANL CANLO DESAT_BOT_L1 DESAT_BOT_L2 DESAT_BOT_L3 FBVDD_MID1 FBVDD_MID2 FBVDD_MID3 FBVDD_SN_L1 FBVDD_SN_L2 FBVDD_SN_L3 FBVDD_VDC-1 FBVDD_VDC-2 FBVDD_VDC-3 FBVEE_MID1 FBVEE_MID2 FBVEE_MID3 FBVEE_SN_L1 FBVEE_SN_L2 FBVEE_SN_L3 FBVEE_VDC-1 FBVEE_VDC-2 FBVEE_VDC-3 GATE_BOT_L1 GATE_BOT_L2 GATE_BOT_L3 GATE_MID_L1 GATE_MID_L2 GATE_MID_L3 GATE_MID_SN_L1 GATE_MID_SN_L2 GATE_MID_SN_L3 GATE_TOP_L1 GATE_TOP_L2 GATE_TOP_L3 GND_ISO_CAN GRID_GND I_MID+ I_MID- I_NEG_RAIL+ I_NEG_RAIL- L1_MID_DRAIN L2_MID_DRAIN L3_MID_DRAIN NetC35_2 NetC156_1 NetC196_1 NetC209_1 NetC228_1 NetC343_1 NetC378_2 NetC454_2 NetD7_2 NetD8_2 NetD10_2 NetD11_2 NetD12_2 NetD14_2 NetD15_2 NetD16_2 NetD17_2 NetD18_1 NetD19_2 NetD20_2 NetD21_2 NetD22_1 NetD23_1 NetD24_1 NetD25_2 NetD26_2 NetD27_2 NetD28_1 NetD29_1 NetD30_1 NetD31_1 NetD32_1 NetD33_1 NetR21_1 NetR31_1 NetR41_1 NetR44_1 NetR51_1 NetR54_1 OC_TOP_L1 OH_BOT_L1 OH_BOT_L2 OH_BOT_L3 OL_BOT_L1 OL_BOT_L2 OL_BOT_L3 OUTH_MID_L1 OUTH_MID_L2 OUTH_MID_L3 OUTH_MID_SN_L1 OUTH_MID_SN_L2 OUTH_MID_SN_L3 OUTH_TOP_L1 OUTH_TOP_L2 OUTH_TOP_L3 OUTL_TOP_L1 OUTL_TOP_L2 OUTL_TOP_L3 PCC_L1 PCC_L2 PCC_L3 REF_MID1 REF_MID2 REF_MID3 REF_SN_L1 REF_SN_L2 REF_SN_L3 REF_VDC-1 REF_VDC-2 REF_VDC-3 RLIM RLIM_MID1 RLIM_MID2 RLIM_MID3 RLIM_SN_L1 RLIM_SN_L2 RLIM_VDC-1 RLIM_VDC-2 RLIM_VDC-3 V_PCC_L1 V_PCC_L2 V_PCC_L3 V_PCC_N V_SN_N VDC+ VDC- VDC-_REF VDC_MID VDC_MID_IN VDC_NEG_IN VEEA_MID1 VEEA_MID2 VEEA_MID3 VEEA_SN_L1 VEEA_SN_L2 VEEA_SN_L3 VEEA_VDC-1 VEEA_VDC-2 VEEA_VDC-3 VIN_PWR_CAN VINN_DC- VINN_VMD VINP_DC- VINP_VMD VISOOUT VP_CAN VP_CAN_SUBD
component class U_TIDA-1606-SW-Current-Measurements-E7: C100 C166 C167 C169 C180 C310 C311 C312 C313 C316 C328 C329 C335 C425 C429 C430 R176 R177 R178 R179 R180 R181 R183 R184 R185 R306 R307 R308 R309 R310 R311 R312 R313 R314 R339 R340 R344 R345 R346 R347 R348 R349 R352 U9 U21 U41 U47
component class U_TIDA-1606-Switching-Node-L3-E7: C132 C133 C134 C135 C138 C143 C144 C145 C146 C147 C148 C149 C150 C151 C152 C153 C154 C155 C156 C157 C158 C159 C160 C161 C162 C163 C165 C340 C437 C475 D7 D8 D31 FB21 NT18 R80 R81 R147 R148 R149 R150 R151 R152 R153 R155 R156 R157 R158 R159 R160 R161 R162 R163 R164 R165 R166 R167 R169 R172 R174 R175 R182 R318 R364 TP8 U17 U19 U20 U22
component class U_TIDA-1606-Switching-Node-L2-E7: C137 C164 C241 C279 C280 C315 C317 C318 C319 C320 C321 C325 C330 C331 C332 C333 C334 C336 C337 C338 C339 C341 C343 C345 C347 C349 C350 C352 C439 C480 D16 D17 D33 FB23 NT22 R99 R264 R268 R283 R284 R315 R316 R317 R319 R320 R321 R323 R324 R325 R327 R328 R329 R330 R331 R332 R333 R334 R335 R336 R337 R338 R341 R350 R450 TP23 U43 U45 U46 U48
component class U_TIDA-1606-Switching-Node-L1-E7: C136 C139 C140 C141 C142 C170 C171 C276 C277 C278 C282 C287 C288 C289 C290 C291 C293 C294 C296 C298 C299 C300 C303 C304 C306 C307 C309 C344 C438 C479 D14 D15 D32 FB22 NT21 R88 R93 R154 R173 R246 R259 R260 R277 R278 R279 R282 R285 R286 R288 R289 R290 R291 R292 R293 R294 R295 R296 R297 R298 R301 R303 R305 R322 R448 TP20 U36 U38 U39 U42
component class U_TIDA-1606-Middle-Side-E7: C201 C214 C232 C233 C234 C235 C236 C237 C238 C239 C242 C243 C244 C245 C246 C247 C248 C249 C250 C251 C252 C253 C254 C255 C256 C257 C258 C259 C260 C261 C262 C263 C264 C265 C266 C269 C270 C271 C272 C273 C274 C275 C397 C398 C399 C400 C402 C403 C404 C405 C406 C407 C408 C410 C411 C412 C434 C435 C436 D25 D26 D27 D28 D29 D30 FB13 FB14 FB15 L8 NT20 NT23 NT24 R85 R86 R87 R224 R226 R242 R248 R249 R250 R254 R255 R256 R257 R258 R261 R262 R263 R265 R266 R267 R269 R270 R271 R272 R273 R274 R275 R276 R280 R342 R361 R363 R447 R505 R506 R507 R508 R509 R510 R511 R512 R513 R514 R530 R531 R538 R539 R565 R566 R567 R568 R569 R570 TP50 TP51 TP52 TP53 TP54 TP55 TP56 TP57 TP58 U29 U30 U31 U32 U33 U34 U55 U56
component class U_TIDA-1606-Low-Side-E7: C172 C173 C174 C178 C179 C181 C182 C183 C184 C185 C186 C187 C188 C189 C190 C191 C192 C193 C194 C195 C196 C199 C200 C202 C203 C204 C205 C206 C207 C208 C209 C212 C213 C215 C216 C217 C218 C219 C220 C221 C222 C223 C224 C225 C226 C227 C228 C230 C413 C414 C415 C416 C418 C419 C420 C421 C422 C423 C424 C426 C427 C428 C431 C432 C433 C450 C451 C476 C477 C478 D10 D11 D12 D19 D20 D21 D22 D23 D24 FB10 FB11 FB12 L7 NT9 NT19 NT25 NT26 R82 R83 R84 R186 R187 R188 R189 R190 R191 R193 R194 R195 R196 R197 R198 R199 R200 R201 R202 R203 R204 R205 R206 R208 R210 R211 R212 R213 R214 R215 R216 R217 R218 R219 R220 R221 R223 R227 R228 R229 R230 R231 R232 R233 R234 R235 R236 R237 R238 R239 R240 R241 R243 R244 R245 R252 R253 R281 R302 R351 R353 R446 R527 R528 R529 R532 R533 R534 R535 R536 R537 R540 R541 R542 R555 R556 R557 R560 R561 R562 TP11 TP12 TP14 TP17 TP41 TP42 TP43 TP44 TP45 TP46 TP47 TP48 TP49 U8 U23 U25 U26 U27 U28 U57 U58
component class U_TIDA-1606-Hardware-E7: !PCB C103 C104 C366 C367 C368 C369 C401 C417 D6 FID1 FID2 FID3 J19 J20 J21 LBL1 Logo1 LOGO2 Logo3 Logo4 LOGO5 LOGO6 LOGO7 LOGO8 LOGO9 LOGO10 LOGO11 LOGO12 LOGO13 MP1 MP2 MP3 MP4 MP5 MP6 MP7 MP8 MP9 MP10 MP11 MP12 MP13 MP14 MP15 MP16 MP17 MP18 MP19 MP20 MP21 MP22 MP23 MP24 MP25 MP26 Q15 R117 R118 R119 R120 R121 R122 R123 R124 R125 R126 R127 R128 R129 R130 R131 TP63 TP64 U13 ZZ1 ZZ2 ZZ3 ZZ4
component class U_TIDA-1606-SW-Voltage-Measurements-E7: C56 C57 C58 C59 C60 C61 C62 C63 C64 C65 C66 C197 C231 C348 C351 C353 C354 C355 C356 C358 C359 C361 C362 C363 C364 C445 L12 R63 R65 R68 R70 R73 R75 R76 RN1 RN2 RN3 U18 U37 U40 U60
component class U_TIDA-1606-PCC-Voltage-Measurements-E7: C198 C210 C211 C229 C240 C267 C268 C281 C283 C284 C285 C295 C297 C301 C302 C305 C308 C322 C323 C324 C326 C327 C357 C447 C448 C449 L14 R171 R207 R222 R225 R247 R251 R300 RN4 RN5 RN6 U35 U44 U49 U59
component class U_TIDA-1606-DC-Voltage-Measurements-E7: C28 C29 C30 C31 C32 C33 C35 C175 C176 C177 C286 C292 C342 C346 C360 C409 C443 C444 C446 C454 C455 C456 C457 L11 R19 R20 R21 R22 R23 R24 R25 R26 R27 R28 R29 R30 R31 R32 R33 R34 R37 TP10 U24 U61 U62 U63
component class U_TIDA-1606-E7-Aux-Supply: C1 C2 C3 C4 C5 C6 C8 C9 C10 C11 C12 C13 C14 C15 C16 C17 C18 C19 C20 C21 C22 C23 C24 C25 C26 C27 C314 C440 C441 C442 C452 C483 C484 D1 D2 D3 FB24 FB25 J1 J2 J3 J4 J5 J6 J8 J10 J11 J12 J31 L6 L9 Q1 R1 R2 R3 R4 R5 R6 R7 R8 R9 R11 R12 R13 R14 R15 R16 R17 R18 R35 TP1 TP2 TP3 TP4 TP5 U1 U2 U3 U4 U5 U6 U7 U66
component class U_TIDA-1606-Control-Interface-E7: C34 C102 C168 C383 C384 C385 C386 C387 C388 C389 C390 C391 C392 C393 C394 C461 C462 C463 C464 C465 C466 C467 C468 C469 C470 C471 C472 C473 C474 C481 C485 C486 C487 C488 C489 C490 C492 C? J26 J27 J29 Q16 R10 R62 R101 R102 R103 R105 R106 R107 R108 R110 R112 R114 R116 R140 R143 R145 R168 R170 R192 R209 R287 R299 R304 R326 R343 R354 R355 R356 R357 R358 R359 R360 R362 R365 R366 R367 R374 R375 R376 R377 R378 R379 R380 R381 R388 R389 R390 R392 R393 R396 R398 R399 R403 R404 R411 R412 R413 R414 R415 R422 R424 R433 R434 R435 R436 R437 R438 R439 R440 R441 R442 R443 R444 R445 R449 R452 R455 R457 R458 R459 R460 R461 R462 R463 R464 R465 R466 R467 R469 R470 R471 R472 R475 R476 R477 R478 R481 R? S1 S2 S3 S4 S5 S? TP9 TP15 TP16 TP18 TP19 TP26 U51 U52 U53 U54
component class U_TIDA-1606-CAN-Communication-E7: C370 C371 C372 C373 C374 C375 C376 C377 C378 C379 C380 C381 C382 D18 FB16 FB17 FB18 FB19 FB20 J22 J23 J24 J25 L13 R382 R383 R384 R385 R386 R387 U50 U64 U65
component class Label: LBL1
component class Header: J1 J2 J8 J10 J11 J12 J25 J27 J31
component class FiducialMark: FID1 FID2 FID3
component class AssemblyNote: ZZ1 ZZ2 ZZ3 ZZ4
component class U_TIDA-1606-PCC-Current-Measurements-E7: C105 C106 C107 C108 C109 C110 C111 C112 C113 C114 C115 C116 C117 C118 C119 C120 C121 C122 C123 C124 C125 C126 C127 C128 C129 C130 C131 FB1 FB2 FB3 FB4 FB5 FB6 FB7 FB8 FB9 R132 R133 R134 R135 R136 R137 R138 R139 R141 R142 R144 R146 TP13 U14 U15 U16
component class U_TIDA-1606-EMI-Protection-E7: C7 C67 C68 C69 C70 C71 C72 C73 C74 C75 C76 C77 C78 C79 C80 C81 C82 C83 C84 C85 C86 C87 C88 C89 C90 C91 C92 C93 C94 C95 C96 C97 C98 C99 C101 C365 D4 D5 F1 F2 F3 K1 K2 K3 L4 L5 NT17 Q14 R36 R38 R39 R40 R61 R64 R66 R67 R69 R71 R72 R74 R77 R78 R79 R89 R90 R91 R92 R94 R95 R96 R97 R98 R100 R104 R109 R111 R113 R115 TP6 TP7 TP21 TP22 TP24 TP25 TP27 TP28 TP35 TP36 TP37 TP38 TP39 TP40 U10 U11 U12
component class TIDA-1606-Overview-E7: C36 C37 C38 C39 C40 C41 C42 C43 C44 C45 C46 C47 C48 C49 C50 C51 C52 C53 C54 C55 C395 C396 C458 C459 C460 J13 J14 J15 J16 J17 J18 J30 L1 L2 L3 Q2 Q3 Q4 Q5 Q6 Q7 Q8 Q9 Q10 Q11 Q12 Q13 R41 R42 R43 R44 R45 R46 R47 R48 R49 R50 R51 R52 R53 R54 R55 R56 R57 R58 R59 R60 TP29 TP30 TP31 TP32 TP33 TP34 TP59 TP60 TP61 TP62 TP65 TP66 TP67

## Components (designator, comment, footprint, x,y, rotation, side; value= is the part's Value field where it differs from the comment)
C1 "C1608X7R1V105K080AC" 0603 97.13,335.102 r90 top value=1uF
C2 "GCM155R71H104KE02D" 0402S 98.45,334.813 r90 top value=0.1uF
C3 "C1608X7R1V105K080AC" 0603 103.327,335.61 r90 top value=1uF
C4 "GRM188R72A272KA01D" 0603 98.51,339.012 r90 top value=2700pF
C5 "C0603X332K5RACTU" 0603 102.808,339.012 r90 top value=3300pF
C6 "GRM155R71E104KE14D" 0402L 108.479,328.87 r270 top value=0.1uF
C7 "GRM155R71H472KA01D" 0402 67.902,138.801 r270 top value=4700pF
C8 "GRM1885C2A220JA01D" 0603 123.245,326.679 r180 top value=22pF
C9 "GRM32ER71A476KE15L" 1210_270 116.504,320.199 r0 top value=47uF
C10 "GRM32ER71A476KE15L" 1210_270 116.502,316.8 r0 top value=47uF
C11 "GRM32ER71E226KE15L" 1210_270 116.504,323.605 r0 top value=22uF
C12 "EMK212BB7106KG-T" 0805_HV 116.52,331.894 r180 top value=10uF
C13 "GCM155R71H104KE02D" 0402L 117.344,330.1 r0 top value=0.1uF
C14 "C0603C103K4RACTU" 0603 123.245,331.894 r0 top value=0.01uF
C15 "GRM155R71E104KE14D" 0402L 100.845,324 r270 top value=0.1uF
C16 "EMK212BB7106KG-T" 0805_HV 102.54,323.542 r270 top value=10uF
C17 "EMK107BB7225KA-T" 0603 122.72,297.377 r0 top value=2.2uF
C18 "GRM155R71E104KE14D" 0402L 122.42,295.977 r0 top value=0.1uF
C19 "EMK107BB7225KA-T" 0603 122.738,292.171 r0 top value=2.2uF
C20 "GRM155R71E104KE14D" 0402L 100.221,321.5 r0 top value=0.1uF
C21 "EMK212BB7106KG-T" 0805_HV 100.737,319.7 r180 top value=10uF
C22 "EMK107BB7225KA-T" 0603 2.5,124.161 r0 top value=2.2uF
C23 "GRM155R71E104KE14D" 0402L 2.4,122.8 r0 top value=0.1uF
C24 "EMK107BB7225KA-T" 0603 4.588,120.017 r90 top value=2.2uF
C25 "EMK107BB7225KA-T" 0603 76.84,125.532 r0 top value=2.2uF
C26 "GRM155R71E104KE14D" 0402L 76.54,124.108 r0 top value=0.1uF
C27 "EMK107BB7225KA-T" 0603 76.84,120.318 r0 top value=2.2uF
C28 "EMK107BB7225KA-T" 0603 159,46.387 r0 top value=2.2uF
C29 "GRM155R71E104KE14D" 0402L 159.101,45.1 r180 top value=0.1uF
C30 "GRM155R71E104KE14D" 0402L 91.602,315.698 r180 top value=0.1uF
C31 "EMK107BB7225KA-T" 0603 91.302,316.998 r180 top value=2.2uF
C32 "CGA2B2C0G1H102J050BA" 0402L 85.27,311.462 r90 top value=1000pF
C33 "GRM1555C1H102JA01D" 0402L 161.9,47.3 r0 top value=1000pF
C34 "EMK107BB7225KA-T" 0603L 59.934,289.2 r0 top value=2.2uF
C35 "GRM155R71H102KA01D" 0402L 167.401,31.456 r90 top value=1000pF
C36 "ALA8DA241CD500" FP-ALA8DA241CD500_RADIAL-MFG 189.315,50.314 r180 bottom value=240µF
C37 "B32774H8395K000" FP-B32774H8395K000_RADIAL-MFG 253.727,234.974 r0 bottom value=3.9µF
C38 "B58043E5254M052" FP-B58043E5254M052_2220-MFG 207.118,279.791 r270 top value=250nF
C39 "B58043E5254M052" FP-B58043E5254M052_2220-MFG 207.014,188.79 r270 top value=250nF
C40 "B58043E5254M052" FP-B58043E5254M052_2220-MFG 213.252,97.821 r270 top value=250nF
C41 "ALA8DA241CD500" FP-ALA8DA241CD500_RADIAL-MFG 221.809,50.314 r180 bottom value=240µF
C42 "B32774H8395K000" FP-B32774H8395K000_RADIAL-MFG 253.727,144 r0 bottom value=3.9µF
C43 "B58043E5254M052" FP-B58043E5254M052_2220-MFG 213.252,279.791 r270 top value=250nF
C44 "B58043E5254M052" FP-B58043E5254M052_2220-MFG 213.11,188.79 r270 top value=250nF
C45 "B58043E5254M052" FP-B58043E5254M052_2220-MFG 207.156,97.821 r270 top value=250nF
C46 "ALA8DA241CD500" FP-ALA8DA241CD500_RADIAL-MFG 178.924,17.802 r0 bottom value=240µF
C47 "B32774H8395K000" FP-B32774H8395K000_RADIAL-MFG 253.727,250.994 r180 bottom value=3.9µF
C48 "B58043E5254M052" FP-B58043E5254M052_2220-MFG 213.252,291.601 r270 top value=250nF
C49 "B58043E5254M052" FP-B58043E5254M052_2220-MFG 207.073,200.206 r270 top value=250nF
C50 "B58043E5254M052" FP-B58043E5254M052_2220-MFG 213.252,109.346 r270 top value=250nF
C51 "ALA8DA241CD500" FP-ALA8DA241CD500_RADIAL-MFG 244.189,17.802 r90 bottom value=240µF
C52 "B32774H8395K000" FP-B32774H8395K000_RADIAL-MFG 253.727,160 r180 bottom value=3.9µF
C53 "B58043E5254M052" FP-B58043E5254M052_2220-MFG 207.118,291.601 r270 top value=250nF
C54 "B58043E5254M052" FP-B58043E5254M052_2220-MFG 213.169,200.206 r270 top value=250nF
C55 "B58043E5254M052" FP-B58043E5254M052_2220-MFG 207.156,109.346 r270 top value=250nF
C56 "EMK107BB7225KA-T" 0603 107.097,221.062 r0 top value=2.2uF
C57 "GRM155R71E104KE14D" 0402L 106.8,222.399 r180 top value=0.1uF
C58 "GRM155R71E104KE14D" 0402L 91.578,222.4 r0 top value=0.1uF
C59 "EMK107BB7225KA-T" 0603 91.278,221.062 r180 top value=2.2uF
C60 "CGA2B2C0G1H102J050BA" 0402L 106.297,224.162 r90 top value=1000pF
C61 "GRM1555C1H101JA01D" 0402L 62.602,328.87 r90 top value=100pF
C62 "GRM155R71E104KE14D" 0402L 92.12,225.439 r90 top value=0.1uF
C63 "EMK107BB7225KA-T" 0603 107.773,214.037 r270 top value=2.2uF
C64 "GRM155R71E104KE14D" 0402L 106.3,214.334 r90 top value=0.1uF
C65 "GRM155R71E104KE14D" 0402L 91.578,214.834 r0 top value=0.1uF
C66 "EMK107BB7225KA-T" 0603 91.278,213.5 r180 top value=2.2uF
C67 "B58043E5254M052" FP-B58043E5254M052_2220-MFG 163.842,210.526 r0 top value=250nF
C68 "R523R447050P1M" FP-R523R447050P1M_RADIAL-MFG 114.687,229.201 r135 bottom value=4.7µF
C69 "R523R447050P1M" FP-R523R447050P1M_RADIAL-MFG 114.315,190.268 r225 bottom value=4.7µF
C70 "R523R447050P1M" FP-R523R447050P1M_RADIAL-MFG 114.271,138.889 r135 bottom value=4.7µF
C71 "B58043E5254M052" FP-B58043E5254M052_2220-MFG 163.842,204.474 r0 top value=250nF
C72 "B58043E5254M052" FP-B58043E5254M052_2220-MFG 163.757,108.215 r0 top value=250nF
C73 "B58043E5254M052" FP-B58043E5254M052_2220-MFG 163.757,114.266 r0 top value=250nF
C74 "R413F147050T1K" FP-R413F147050T1K_RADIAL-MFG 131.067,122.536 r45 bottom value=4.7nF
C75 "B58043E5254M052" FP-B58043E5254M052_2220-MFG 163.842,198.422 r0 top value=250nF
C76 "B58043E5254M052" FP-B58043E5254M052_2220-MFG 163.757,120.318 r0 top value=250nF
C77 "R523R447050P1M" FP-R523R447050P1M_RADIAL-MFG 42.806,157.132 r180 bottom value=4.7µF
C78 "R523R447050P1M" FP-R523R447050P1M_RADIAL-MFG 42.806,124.985 r180 bottom value=4.7µF
C79 "R523R447050P1M" FP-R523R447050P1M_RADIAL-MFG 42.806,140.849 r180 bottom value=4.7µF
C80 "R413F147050T1K" FP-R413F147050T1K_RADIAL-MFG 55.215,112.196 r180 bottom value=4.7nF
C81 "DK1B3EA681K86RBH01" FP-DK1B3EA681K86RBH01_SMD2-MFG 51.456,133.295 r180 top value=680pF
C82 "DK1B3EA681K86RBH01" FP-DK1B3EA681K86RBH01_SMD2-MFG 51.456,118.325 r180 top value=680pF
C83 "DK1B3EA681K86RBH01" FP-DK1B3EA681K86RBH01_SMD2-MFG 51.456,149.17 r180 top value=680pF
C84 "EVA86Q7UTF472KA01K" FP-EVA86Q7UTF472KA01K_SMD2-MFG 63.347,148.071 r90 top value=4.7nF
C85 "CL31B106KBHNNNE" 1206_180L 64.446,167.695 r270 top value=10uF
C86 "CL31B106KBHNNNE" 1206_180L 66.732,167.684 r270 top value=10uF
C87 "GCM155R71H104KE02D" 0402S 62.888,166.306 r270 top value=0.1uF
C88 "GRM155R71H472KA01D" 0402 68.675,136.432 r180 top value=4700pF
C89 "GCM155R71H104KE02D" 0402S 49.784,167.613 r270 top value=0.1uF
C90 "CL31B106KBHNNNE" 1206_180L 50,161 r0 top value=10uF
C91 "GRM155R71H223KA12D" 0402 65.981,135.846 r0 top value=0.022uF
C92 "GRM155R71E104KE14D" 0402S 62.183,133.746 r90 top value=0.1uF
C93 "CGA2B2X7R1H331K050BA" 0402S 49.9,164.363 r270 top value=330pF
C94 "GCM155R71H104KE02D" 0402S 87.8,36.49 r90 top value=0.1uF
C95 "GRM155R71E104KE14D" 0402S 65.024,164.668 r0 top value=0.1uF
C96 "GRM155R71E104KE14D" 0402S 66.5,129.556 r270 top value=0.1uF
C97 "CGA3E1X7R1E105M080AC" 0603 60.862,134.193 r90 top value=1uF
C98 "GRM155R71E104KE14D" 0402 87.627,42.7 r90 top value=0.1uF
C99 "CGA2B2C0G1H100D050BA" 0402 67.913,131.488 r90 top value=10pF
C100 "GRM1555C1E751JA01D" 0402L 75.51,332.105 r270 top value=750pF
C101 "CGA2B3X7R1H103K050BB" 0402 69.418,131.488 r90 top value=0.01uF
C102 "GRM1555C1H101JA01D" 0402L 103.446,307.971 r90 top value=100pF
C103 "GRM155R71E104KE14D" 0402L 52.902,328.414 r270 top value=0.1uF
C104 "GRM155R71E104KE14D" 0402L 56.374,341.912 r0 top value=0.1uF
C105 "EMK107BB7225KA-T" 0603 23.312,154.656 r270 top value=2.2uF
C106 "GRM155R71H102KA01D" 0402L 21.965,154.48 r90 top value=1000pF
C107 "GRM155R71E104KE14D" 0402L 9.331,154.739 r270 top value=0.1uF
C108 "GRM155R71E104KE14D" 0402L 22.465,156.856 r0 top value=0.1uF
C109 "GRM155R71E104KE14D" 0402L 22.465,157.856 r0 top value=0.1uF
C110 "EMK107BB7225KA-T" 0603 7.1,157.809 r180 top value=2.2uF
C111 "GRM155R71H102KA01D" 0402L 22.465,159.06 r0 top value=1000pF
C112 "GRM155R71H102KA01D" 0402 8.112,159.06 r0 top value=1000pF
C113 "CGA4J2C0G1H333J125AA" 0805_HV 22.62,161.6 r90 top value=0.033uF
C114 "EMK107BB7225KA-T" 0603 23.188,122.522 r270 top value=2.2uF
C115 "GRM155R71H102KA01D" 0402L 21.965,122.222 r90 top value=1000pF
C116 "GRM155R71E104KE14D" 0402L 9.342,122.492 r270 top value=0.1uF
C117 "GRM155R71E104KE14D" 0402L 22.465,124.598 r0 top value=0.1uF
C118 "GRM155R71E104KE14D" 0402L 22.465,125.598 r0 top value=0.1uF
C119 "EMK107BB7225KA-T" 0603 6.676,125.532 r180 top value=2.2uF
C120 "GRM155R71H102KA01D" 0402L 22.465,126.802 r0 top value=1000pF
C121 "GRM155R71H102KA01D" 0402L 8.212,126.802 r0 top value=1000pF
C122 "CGA4J2C0G1H333J125AA" 0805_HV 22.62,129.342 r90 top value=0.033uF
C123 "EMK107BB7225KA-T" 0603 23.354,138.471 r270 top value=2.2uF
C124 "GRM155R71H102KA01D" 0402L 22.007,138.295 r90 top value=1000pF
C125 "GRM155R71E104KE14D" 0402L 9.363,138.565 r270 top value=0.1uF
C126 "GRM155R71E104KE14D" 0402L 22.507,140.671 r0 top value=0.1uF
C127 "GRM155R71E104KE14D" 0402L 22.507,141.671 r0 top value=0.1uF
C128 "EMK107BB7225KA-T" 0603 6.718,141.605 r180 top value=2.2uF
C129 "GRM155R71H102KA01D" 0402L 22.507,142.875 r0 top value=1000pF
C130 "GRM155R71H102KA01D" 0402L 8.254,142.875 r0 top value=1000pF
C131 "CGA4J2C0G1H333J125AA" 0805_HV 22.662,145.415 r90 top value=0.033uF
C132 "CL31B106KBHNNNE" 1206_180L 188.617,62 r0 top value=10uF
C133 "CL31B106KBHNNNE" 1206_180L 188.618,64.149 r0 top value=10uF
C134 "GCM155R71H104KE02D" 0402S 187.917,65.646 r0 top value=0.1uF
C135 "C2012X7R1V475K125AC" 0805_HV 188.688,80 r180 top value=4.7uF
C136 "C2012X7R1V475K125AC" 0805_HV 188.688,261.978 r180 top value=4.7uF
C137 "C2012X7R1V475K125AC" 0805_HV 188.688,171.03 r180 top value=4.7uF
C138 "GCM155R71H104KE02D" 0402L 187.856,78.54 r0 top value=0.1uF
C139 "C2012X7R1V475K125AC" 0805_HV 201.798,262.881 r0 top value=4.7uF
C140 "C1608X7R1H334K080AC" 0603L 205.152,262.45 r180 top value=0.33uF
C141 "C1608X7R1H334K080AC" 0603L 180.026,262.217 r0 top value=0.33uF
C142 "C2012X7R1V475K125AC" 0805_HV 176.782,262.699 r180 top value=4.7uF
C143 "GRM155R71E104KE14D" 0402S 185.768,64.685 r0 top value=0.1uF
C144 "CGA2B2X7R1H331K050BA" 0402S 184.468,78.634 r180 top value=330pF
C145 "CGA2B2X7R1H331K050BA" 0402S 183.453,80.462 r180 top value=330pF
C146 "GRM1555C1H101JA01D" 0402L 200.3,65.758 r180 top value=100pF
C147 "GCM155R71H104KE02D" 0402L 207.479,79.29 r0 top value=0.1uF
C148 "C2012X7R1V475K125AC" 0805_HV 201.8,80.918 r0 top value=4.7uF
C149 "EMK107BB7225KA-T" 0603L 207.694,80.486 r180 top value=2.2uF
C150 "GCM155R71H104KE02D" 0402L 201.715,79.29 r180 top value=0.1uF
C151 "C1608X7R1H334K080AC" 0603L 205.12,80.486 r180 top value=0.33uF
C152 "GCM155R71H104KE02D" 0402L 205.491,79.29 r0 top value=0.1uF
C153 "C1608X7R1H334K080AC" 0603L 180.028,80.254 r0 top value=0.33uF
C154 "GRM1555C1H101JA01D" 0402L 206.872,64.236 r270 top value=100pF
C155 "GRM155R71E104KE14D" 0402L 207.92,65.858 r0 top value=0.1uF
C156 "GRM1555C1H101JA01D" 0402L 209.8,77.634 r270 top value=100pF
C157 "GRM155R71E104KE14D" 0402L 223.117,88.668 r270 top value=0.1uF
C158 "GRM155R71E104KE14D" 0402L 53.34,333.516 r90 top value=0.1uF
C159 "GRM155R71E104KE14D" 0402L 174.861,64.647 r270 top value=0.1uF
C160 "GCM155R71H104KE02D" 0402L 179.161,79.065 r180 top value=0.1uF
C161 "C2012X7R1V475K125AC" 0805_HV 176.794,80.8 r180 top value=4.7uF
C162 "GRM1555C1H101JA01D" 0402L 176.721,65.073 r0 top value=100pF
C163 "GCM155R71H104KE02D" 0402L 174.351,79.057 r180 top value=0.1uF
C164 "C2012X7R1V475K125AC" 0805_HV 201.836,171.918 r0 top value=4.7uF
C165 "EMK107BB7225KA-T" 0603L 173.535,80.234 r0 top value=2.2uF
C166 "GRM155R71E104KE14D" 0402L 100.8,132.952 r225 top value=0.1uF
C167 "GRM1555C1E751JA01D" 0402L 73.676,330.068 r90 top value=750pF
C168 "EMK107BB7225KA-T" 0603L 58.702,318.9 r90 top value=2.2uF
C169 "GRM1555C1E751JA01D" 0402L 75.535,321.253 r90 top value=750pF
C170 "GRM155R71E104KE14D" 0402L 223.1,270.6 r270 top value=0.1uF
C171 "GRM155R71E104KE14D" 0402L 56.002,332.885 r90 top value=0.1uF
C172 "CL31B106KBHNNNE" 1206_180L 227.341,325.418 r180 top value=10uF
C173 "CL31B106KBHNNNE" 1206_180L 227.341,327.585 r180 top value=10uF
C174 "GCM155R71H104KE02D" 0402S 227.855,323.805 r180 top value=0.1uF
C175 "CGA2B2C0G1H102J050BA" 0402L 85.226,313.724 r90 top value=1000pF
C176 "EMK107BB7225KA-T" 0603 169.5,30.7 r180 top value=2.2uF
C177 "GRM155R71E104KE14D" 0402L 168.838,32 r0 top value=0.1uF
C178 "GCM155R71H104KE02D" 0402L 228,310.8 r180 top value=0.1uF
C179 "C2012X7R1V475K125AC" 0805_HV 227.174,309.247 r0 top value=4.7uF
C180 "GRM155R71E104KE14D" 0402L 76.411,331.6 r90 top value=0.1uF
C181 "EMK107BB7225KA-T" 0603L 232.8,303.2 r90 top value=2.2uF
C182 "C2012X7R1V475K125AC" 0805_HV 227.174,218.3 r0 top value=4.7uF
C183 "GRM155R71E104KE14D" 0402S 230.302,324.505 r180 top value=0.1uF
C184 "CGA2B2X7R1H331K050BA" 0402S 231.457,310.77 r0 top value=330pF
C185 "CGA2B2X7R1H331K050BA" 0402S 232.504,308.958 r0 top value=330pF
C186 "GRM1555C1H101JA01D" 0402L 215.529,323.511 r0 top value=100pF
C187 "GCM155R71H104KE02D" 0402L 208.471,310.072 r180 top value=0.1uF
C188 "C2012X7R1V475K125AC" 0805_HV 214.15,308.449 r180 top value=4.7uF
C189 "EMK107BB7225KA-T" 0603L 208.271,308.895 r0 top value=2.2uF
C190 "GCM155R71H104KE02D" 0402L 214.168,310.096 r0 top value=0.1uF
C191 "C1608X7R1H334K080AC" 0603L 210.798,308.895 r0 top value=0.33uF
C192 "GCM155R71H104KE02D" 0402L 210.459,310.072 r180 top value=0.1uF
C193 "C2012X7R1V475K125AC" 0805_HV 227.159,127.31 r0 top value=4.7uF
C194 "GRM1555C1H101JA01D" 0402L 209.078,325.132 r90 top value=100pF
C195 "GRM155R71E104KE14D" 0402L 208.03,323.511 r180 top value=0.1uF
C196 "GRM1555C1H101JA01D" 0402L 206.152,311.708 r90 top value=100pF
C197 "CGA2B2C0G1H102J050BA" 0402L 106.297,216.604 r90 top value=1000pF
C198 "EMK107BB7225KA-T" 0603 56.252,88.35 r180 top value=2.2uF
C199 "GRM1555C1H101JA01D" 0402L 215.558,232.542 r0 top value=100pF
C200 "GCM155R71H104KE02D" 0402L 208.473,219.108 r180 top value=0.1uF
C201 "C2012X7R1V475K125AC" 0805_HV 178.984,309.1 r0 top value=4.7uF
C202 "EMK107BB7225KA-T" 0603L 208.273,217.927 r0 top value=2.2uF
C203 "GCM155R71H104KE02D" 0402L 214.17,219.127 r0 top value=0.1uF
C204 "C2012X7R1V475K125AC" 0805_HV 214.152,217.48 r180 top value=4.7uF
C205 "GCM155R71H104KE02D" 0402L 210.461,219.104 r180 top value=0.1uF
C206 "C1608X7R1H334K080AC" 0603L 210.8,217.927 r0 top value=0.33uF
C207 "GRM1555C1H101JA01D" 0402L 209.08,234.164 r90 top value=100pF
C208 "GRM155R71E104KE14D" 0402L 208.032,232.543 r180 top value=0.1uF
C209 "GRM1555C1H101JA01D" 0402L 206.154,220.74 r90 top value=100pF
C210 "GRM155R71E104KE14D" 0402L 56.551,86.9 r0 top value=0.1uF
C211 "GRM155R71E104KE14D" 0402L 68.45,96.83 r180 top value=0.1uF
C212 "GRM1555C1H101JA01D" 0402L 215.495,141.547 r0 top value=100pF
C213 "GCM155R71H104KE02D" 0402L 208.473,128.109 r180 top value=0.1uF
C214 "C2012X7R1V475K125AC" 0805_HV 178.8,218.04 r0 top value=4.7uF
C215 "EMK107BB7225KA-T" 0603L 208.273,126.932 r0 top value=2.2uF
C216 "GCM155R71H104KE02D" 0402L 214.17,128.109 r0 top value=0.1uF
C217 "C2012X7R1V475K125AC" 0805_HV 214.152,126.485 r180 top value=4.7uF
C218 "GCM155R71H104KE02D" 0402L 210.461,128.109 r180 top value=0.1uF
C219 "C1608X7R1H334K080AC" 0603L 210.8,126.932 r0 top value=0.33uF
C220 "GRM155R71E104KE14D" 0402L 108.956,1.887 r180 top value=0.1uF
C221 "EMK107BB7225KA-T" 0603L 107.3,1.9 r90 top value=2.2uF
C222 "GRM155R71E104KE14D" 0402L 123.913,1.9 r0 top value=0.1uF
C223 "CGA2B2C0G1H102J050BA" 0402L 85.125,328.386 r180 top value=1000pF
C224 "GCM155R71H223KA55D" 0402L 123.78,3.766 r90 top value=0.022uF
C225 "GRM1555C1H101JA01D" 0402L 209.08,143.169 r90 top value=100pF
C226 "GRM155R71E104KE14D" 0402L 208.03,141.519 r180 top value=0.1uF
C227 "GRM1555C1E301JA01D" 0402L 55.502,327.285 r90 top value=300pF
C228 "GRM1555C1H101JA01D" 0402L 206.154,129.744 r90 top value=100pF
C229 "EMK107BB7225KA-T" 0603 68.75,98.2 r0 top value=2.2uF
C230 "CGA2B2C0G1H102J050BA" 0402L 87.387,328.43 r0 top value=1000pF
C231 "CGA2B2C0G1H102J050BA" 0402L 110.431,124.182 r90 top value=1000pF
C232 "CL31B106KBHNNNE" 1206_180L 178.986,325.264 r180 top value=10uF
C233 "CL31B106KBHNNNE" 1206_180L 178.994,327.406 r180 top value=10uF
C234 "GCM155R71H104KE02D" 0402S 179.659,323.768 r180 top value=0.1uF
C235 "GCM155R71H104KE02D" 0402L 129.619,11.757 r270 top value=0.1uF
C236 "C1608X7R1H334K080AC" 0603L 130.319,10.157 r0 top value=0.33uF
C237 "EMK107BB7225KA-T" 0603L 124.604,11.057 r90 top value=2.2uF
C238 "GCM155R71H104KE02D" 0402L 179.711,310.778 r180 top value=0.1uF
C239 "C2012X7R1V475K125AC" 0805_HV 178.809,127.021 r0 top value=4.7uF
C240 "GRM1555C1H101JA01D" 0402L 63.202,331.592 r90 top value=100pF
C241 "C1608X7R1H334K080AC" 0603L 205.174,171.484 r180 top value=0.33uF
C242 "EMK107BB7225KA-T" 0603L 196.216,127.5 r270 top value=2.2uF
C243 "GRM155R71E104KE14D" 0402S 181.836,324.468 r180 top value=0.1uF
C244 "CGA2B2X7R1H331K050BA" 0402S 183.136,310.776 r0 top value=330pF
C245 "CGA2B2X7R1H331K050BA" 0402S 184.207,308.976 r0 top value=330pF
C246 "GRM155R61H104ME14D" 0402L 194.264,322.568 r0 top value=0.1uF
C247 "GCM155R71H104KE02D" 0402L 188.425,310.268 r0 top value=0.1uF
C248 "C1608X7R1H334K080AC" 0603L 187.576,309.223 r180 top value=0.33uF
C249 "GRM1555C1H101JA01D" 0402L 190.875,324.142 r180 top value=100pF
C250 "GCM155R71H104KE02D" 0402L 193.236,310.268 r0 top value=0.1uF
C251 "C2012X7R1V475K125AC" 0805_HV 190.838,308.7 r0 top value=4.7uF
C252 "EMK107BB7225KA-T" 0603L 194.125,309.223 r180 top value=2.2uF
C253 "GRM155R61H104ME14D" 0402L 194.266,231.6 r0 top value=0.1uF
C254 "GCM155R71H104KE02D" 0402L 188.427,219.3 r0 top value=0.1uF
C255 "C1608X7R1H334K080AC" 0603L 187.578,218.255 r180 top value=0.33uF
C256 "GRM1555C1H101JA01D" 0402L 190.877,233.174 r180 top value=100pF
C257 "GCM155R71H104KE02D" 0402L 193.238,219.3 r0 top value=0.1uF
C258 "C2012X7R1V475K125AC" 0805_HV 190.838,217.751 r0 top value=4.7uF
C259 "EMK107BB7225KA-T" 0603L 194.127,218.255 r180 top value=2.2uF
C260 "GRM155R61H104ME14D" 0402L 194.266,140.605 r0 top value=0.1uF
C261 "GCM155R71H104KE02D" 0402L 188.427,128.305 r0 top value=0.1uF
C262 "C1608X7R1H334K080AC" 0603L 187.578,127.26 r180 top value=0.33uF
C263 "GRM1555C1H101JA01D" 0402L 190.877,143.076 r180 top value=100pF
C264 "GCM155R71H104KE02D" 0402L 193.238,128.305 r0 top value=0.1uF
C265 "C2012X7R1V475K125AC" 0805_HV 190.84,126.735 r0 top value=4.7uF
C266 "EMK107BB7225KA-T" 0603L 194.127,127.26 r180 top value=2.2uF
C267 "GRM155R71E104KE14D" 0402L 67.9,93.8 r270 top value=0.1uF
C268 "EMK107BB7225KA-T" 0603 60.135,78.51 r180 top value=2.2uF
C269 "EMK107BB7225KA-T" 0603L 108.537,10.731 r180 top value=2.2uF
C270 "GRM155R71E104KE14D" 0402L 123.404,10.857 r90 top value=0.1uF
C271 "GRM155R71E104KE14D" 0402L 108.737,11.8 r180 top value=0.1uF
C272 "CGA2B2C0G1H102J050BA" 0402L 83.847,320.059 r180 top value=1000pF
C273 "GCM155R71H223KA55D" 0402L 123.78,13.74 r90 top value=0.022uF
C274 "GRM1555C1E301JA01D" 0402L 56.01,329.37 r180 top value=300pF
C275 "CGA2B2C0G1H102J050BA" 0402L 86.114,320.059 r0 top value=1000pF
C276 "CL31B106KBHNNNE" 1206_180L 188.598,245.785 r0 top value=10uF
C277 "CL31B106KBHNNNE" 1206_180L 188.598,243.623 r0 top value=10uF
C278 "GCM155R71H104KE02D" 0402S 187.888,247.388 r0 top value=0.1uF
C279 "C1608X7R1H334K080AC" 0603L 180.067,171.251 r0 top value=0.33uF
C280 "C2012X7R1V475K125AC" 0805_HV 176.8,171.732 r180 top value=4.7uF
C281 "GRM155R71E104KE14D" 0402L 60.435,77.06 r0 top value=0.1uF
C282 "GCM155R71H104KE02D" 0402L 187.931,260.432 r0 top value=0.1uF
C283 "GRM155R71E104KE14D" 0402L 71.876,86.896 r180 top value=0.1uF
C284 "EMK107BB7225KA-T" 0603 72.176,88.266 r0 top value=2.2uF
C285 "GRM21BZ71A226ME15L" 0805_HV 68.7,104.783 r90 top value=22uF
C286 "CGA2B3X7R1H153K050BB" 0402L 142.301,32.2 r0 top value=0.015uF
C287 "GRM155R71E104KE14D" 0402S 185.766,246.646 r0 top value=0.1uF
C288 "CGA2B2X7R1H331K050BA" 0402S 184.466,260.598 r180 top value=330pF
C289 "CGA2B2X7R1H331K050BA" 0402S 183.451,262.425 r180 top value=330pF
C290 "GRM1555C1H101JA01D" 0402L 200.298,247.719 r180 top value=100pF
C291 "GCM155R71H104KE02D" 0402L 207.477,261.254 r0 top value=0.1uF
C292 "CGA2B3X7R1H153K050BB" 0402L 143.585,45.014 r180 top value=0.015uF
C293 "EMK107BB7225KA-T" 0603L 207.692,262.45 r180 top value=2.2uF
C294 "GCM155R71H104KE02D" 0402L 201.798,261.254 r180 top value=0.1uF
C295 "GRM21BZ71A226ME15L" 0805_HV 52.524,105.5 r270 top value=22uF
C296 "GCM155R71H104KE02D" 0402L 205.489,261.254 r0 top value=0.1uF
C297 "CGA2B2C0G1H102J050BA" 0402L 53.285,94.971 r270 top value=1000pF
C298 "GRM1555C1H101JA01D" 0402L 206.87,246.198 r270 top value=100pF
C299 "GRM155R71E104KE14D" 0402L 207.918,247.819 r0 top value=0.1uF
C300 "GRM1555C1H101JA01D" 0402L 209.798,259.598 r270 top value=100pF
